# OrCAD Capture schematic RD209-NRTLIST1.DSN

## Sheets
1 4: size A3
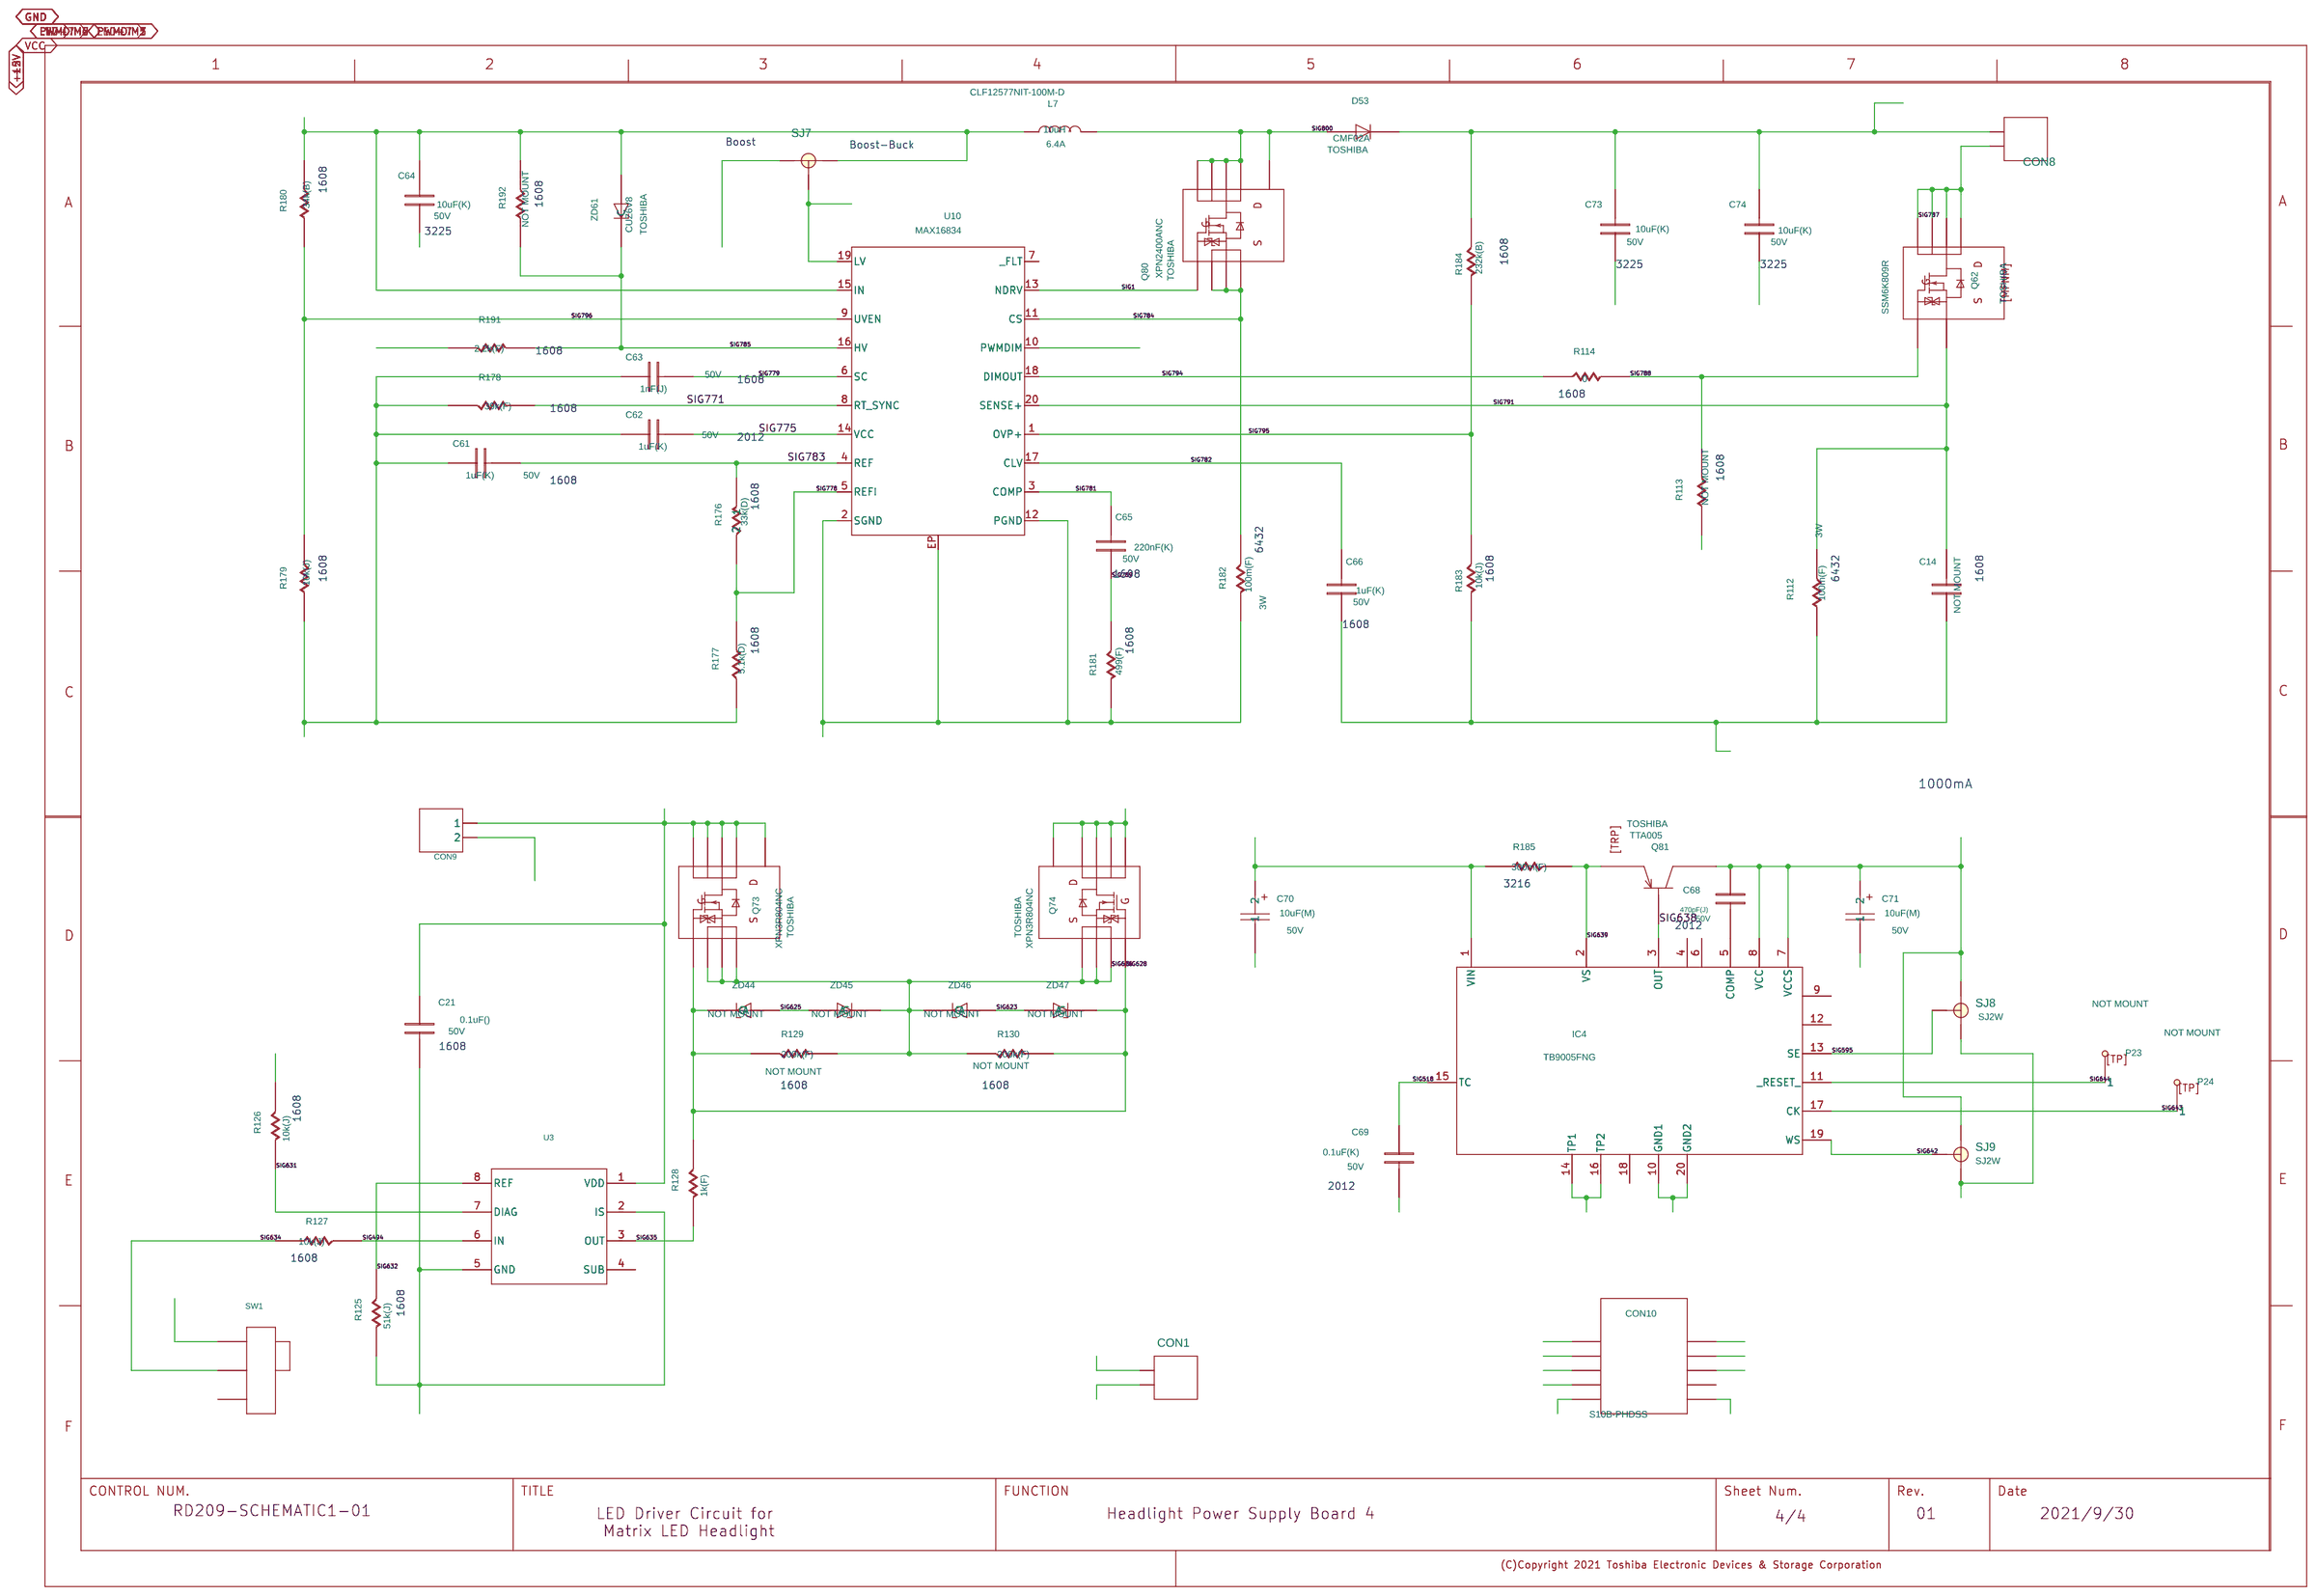
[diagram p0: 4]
2 3: size A3
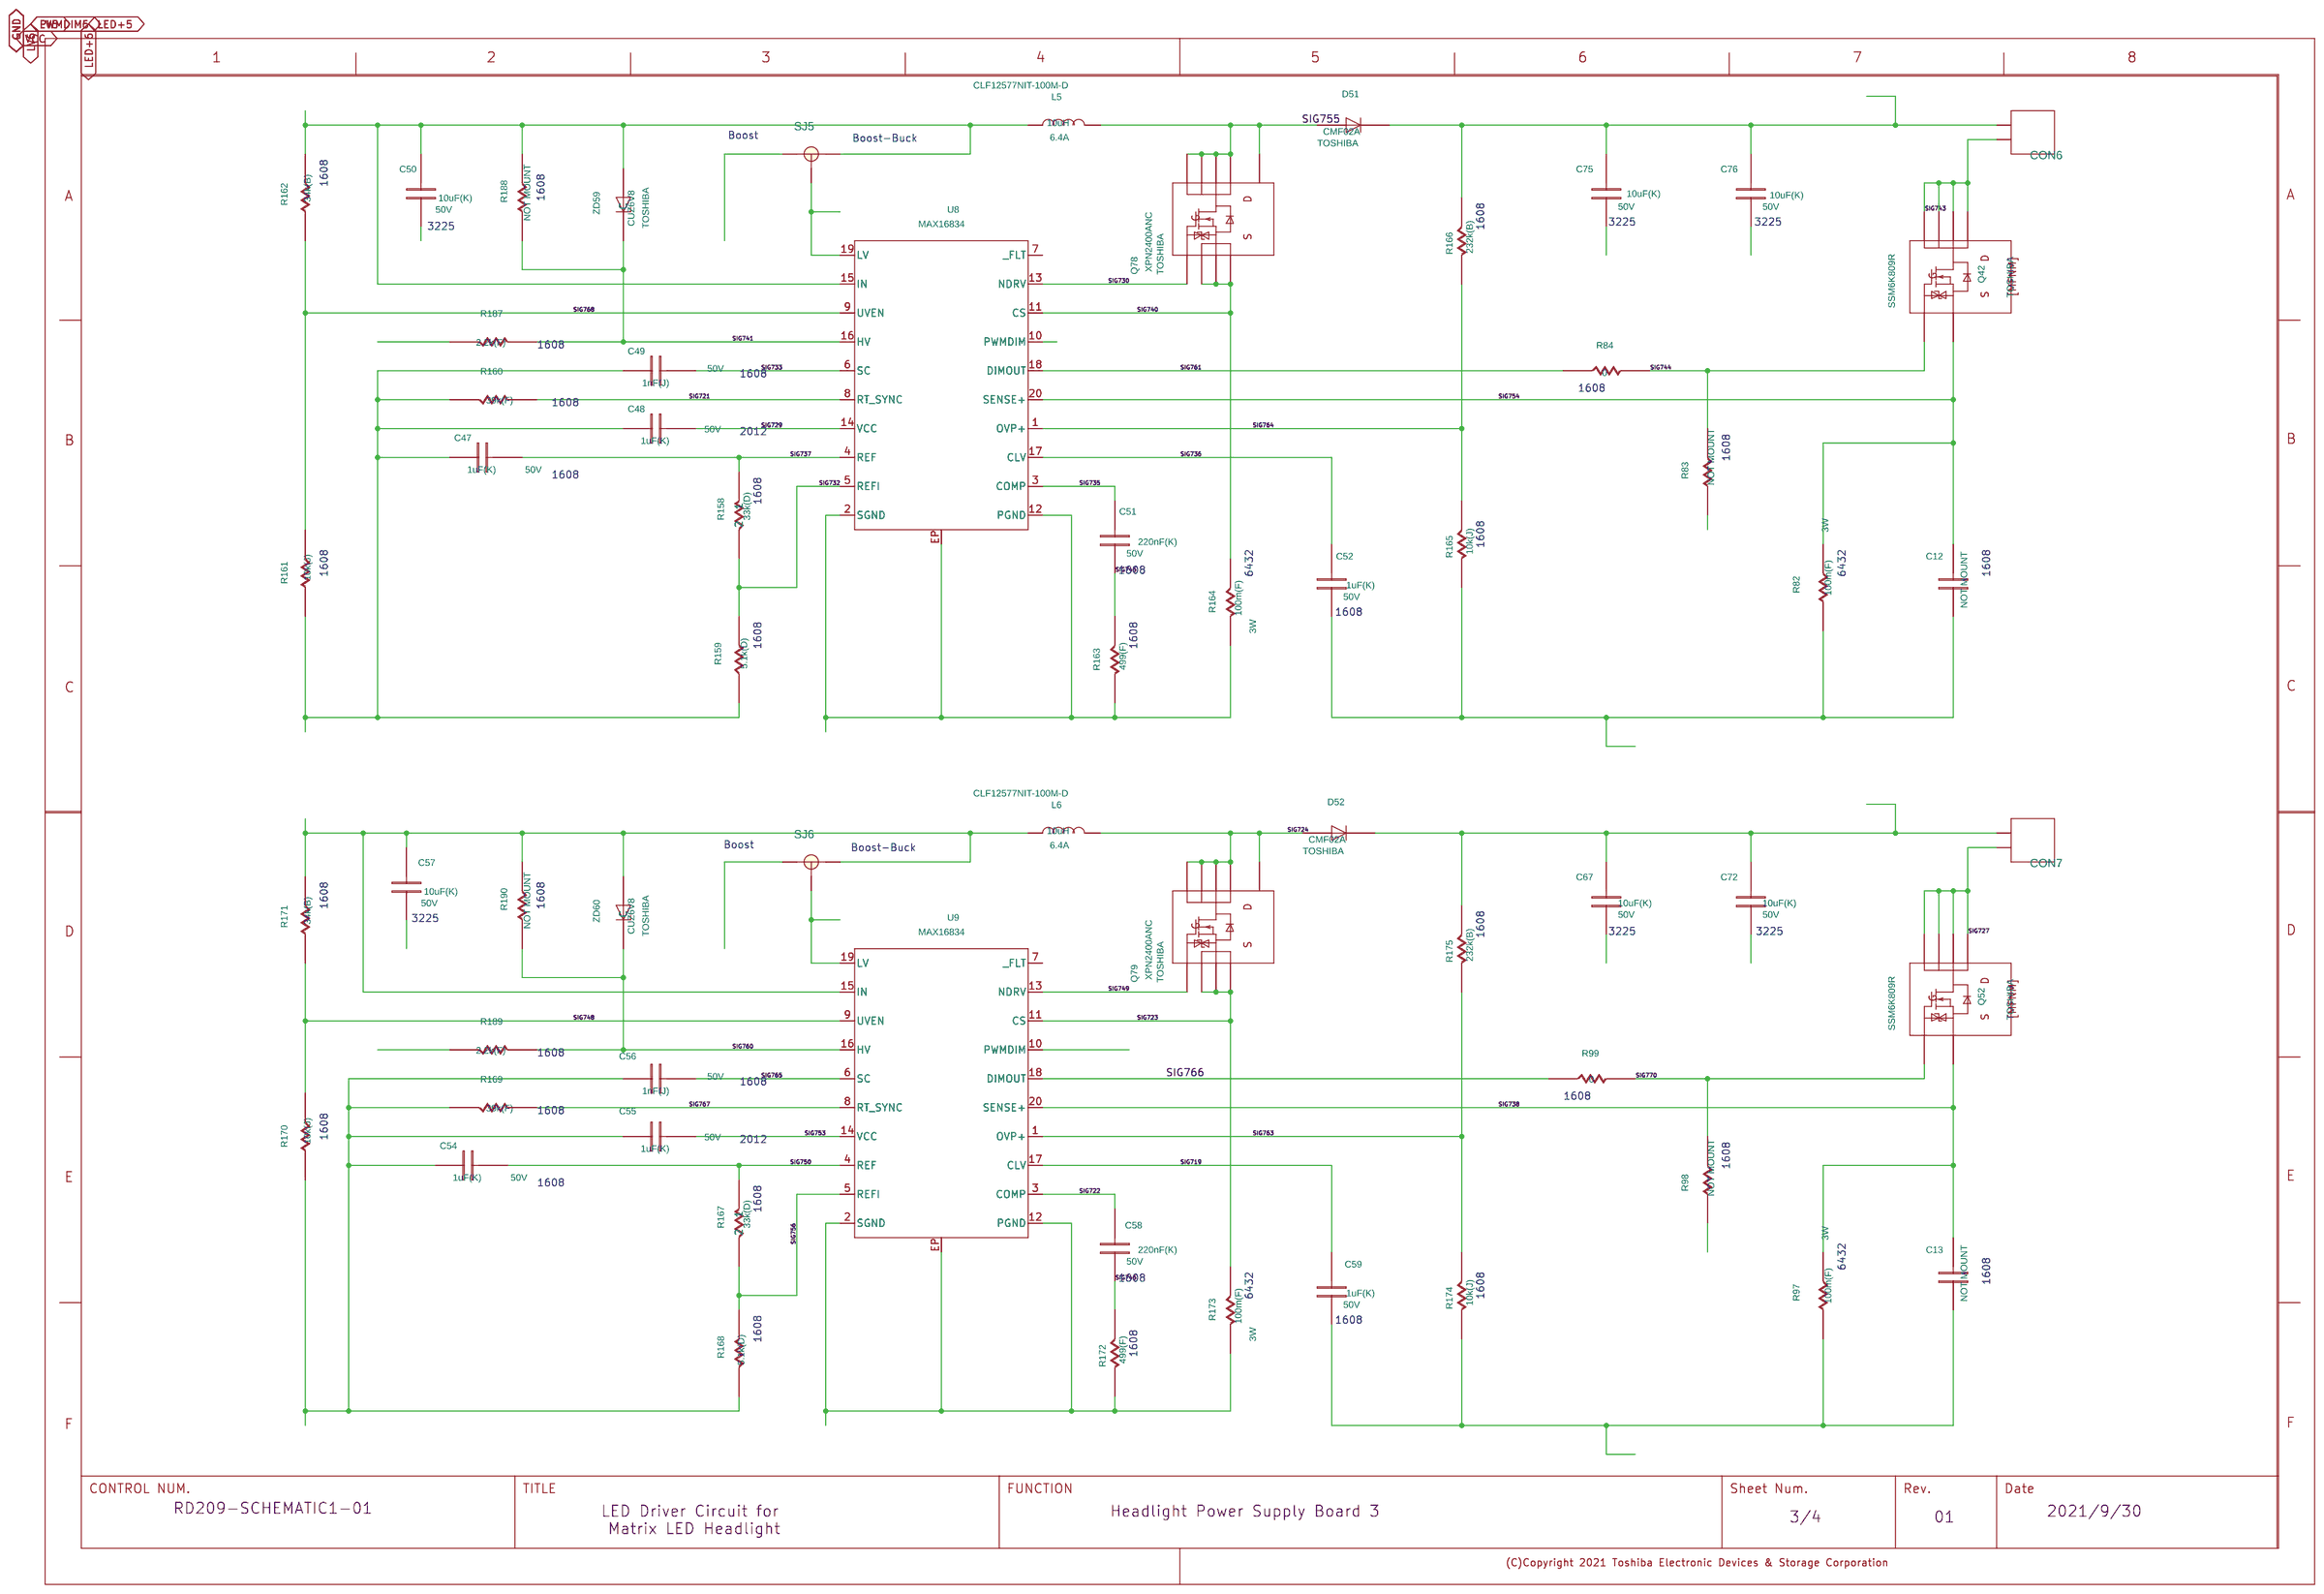
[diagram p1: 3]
3 2: size A3
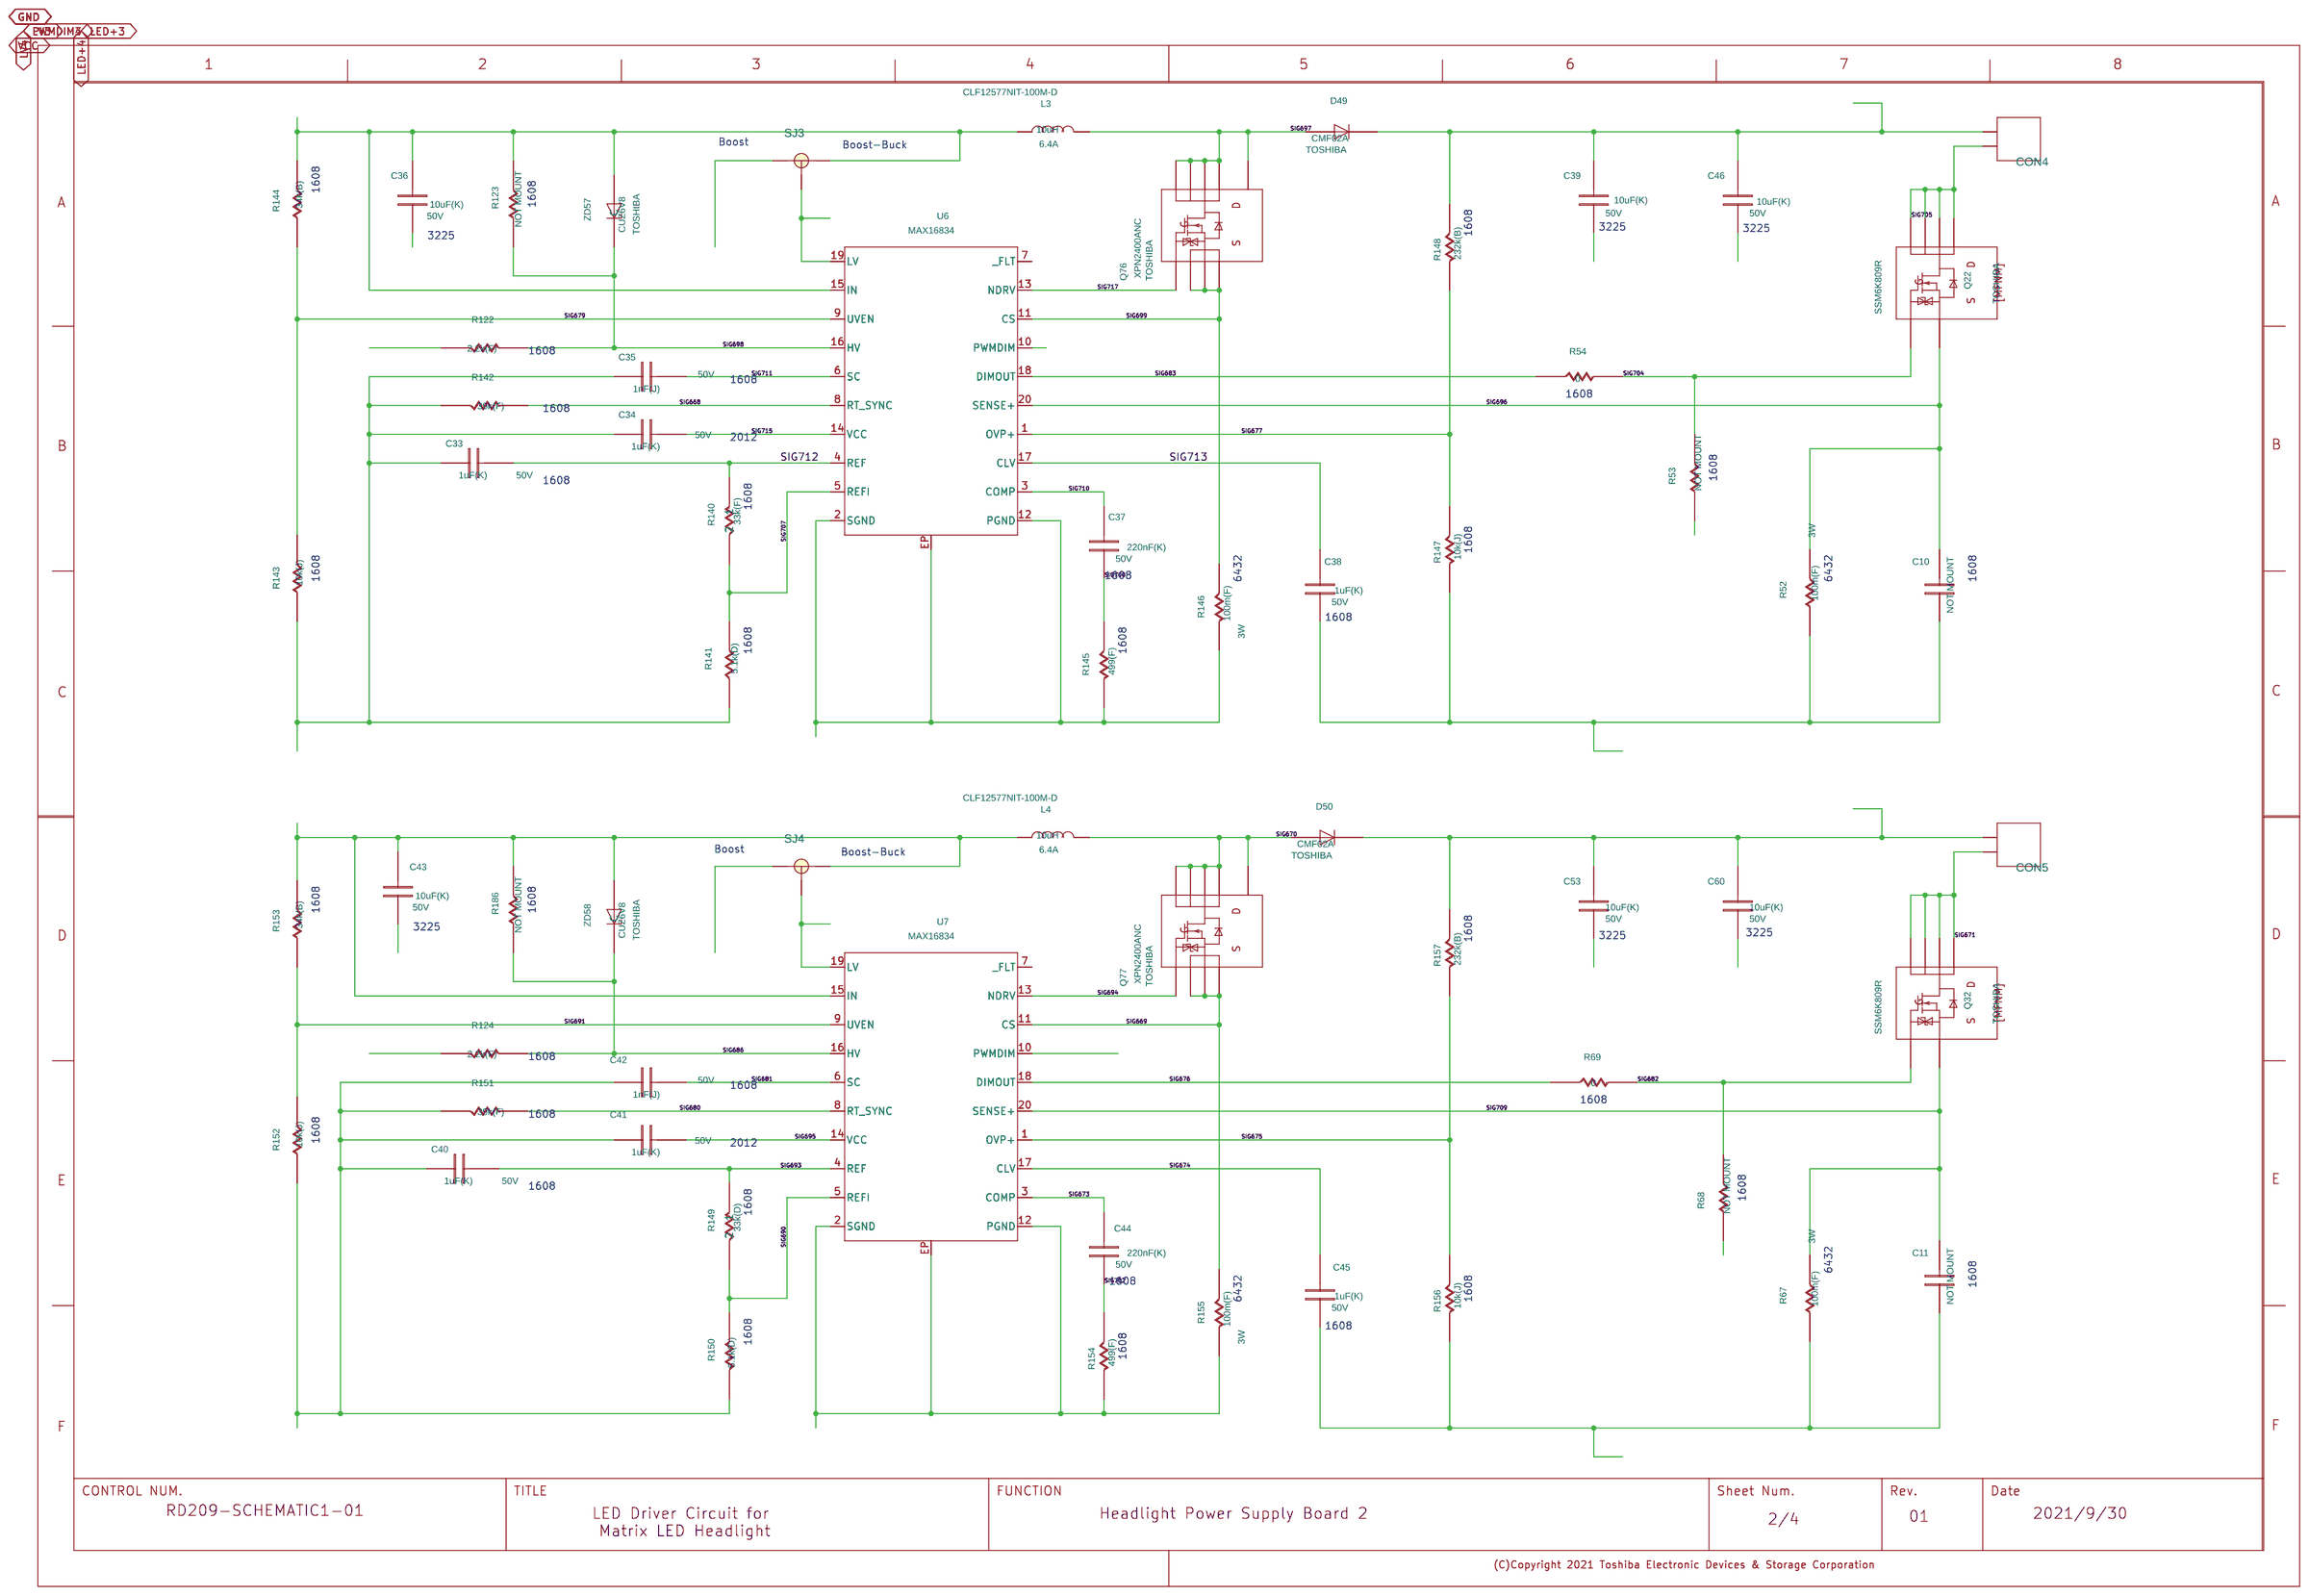
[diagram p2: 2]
4 1: size A3
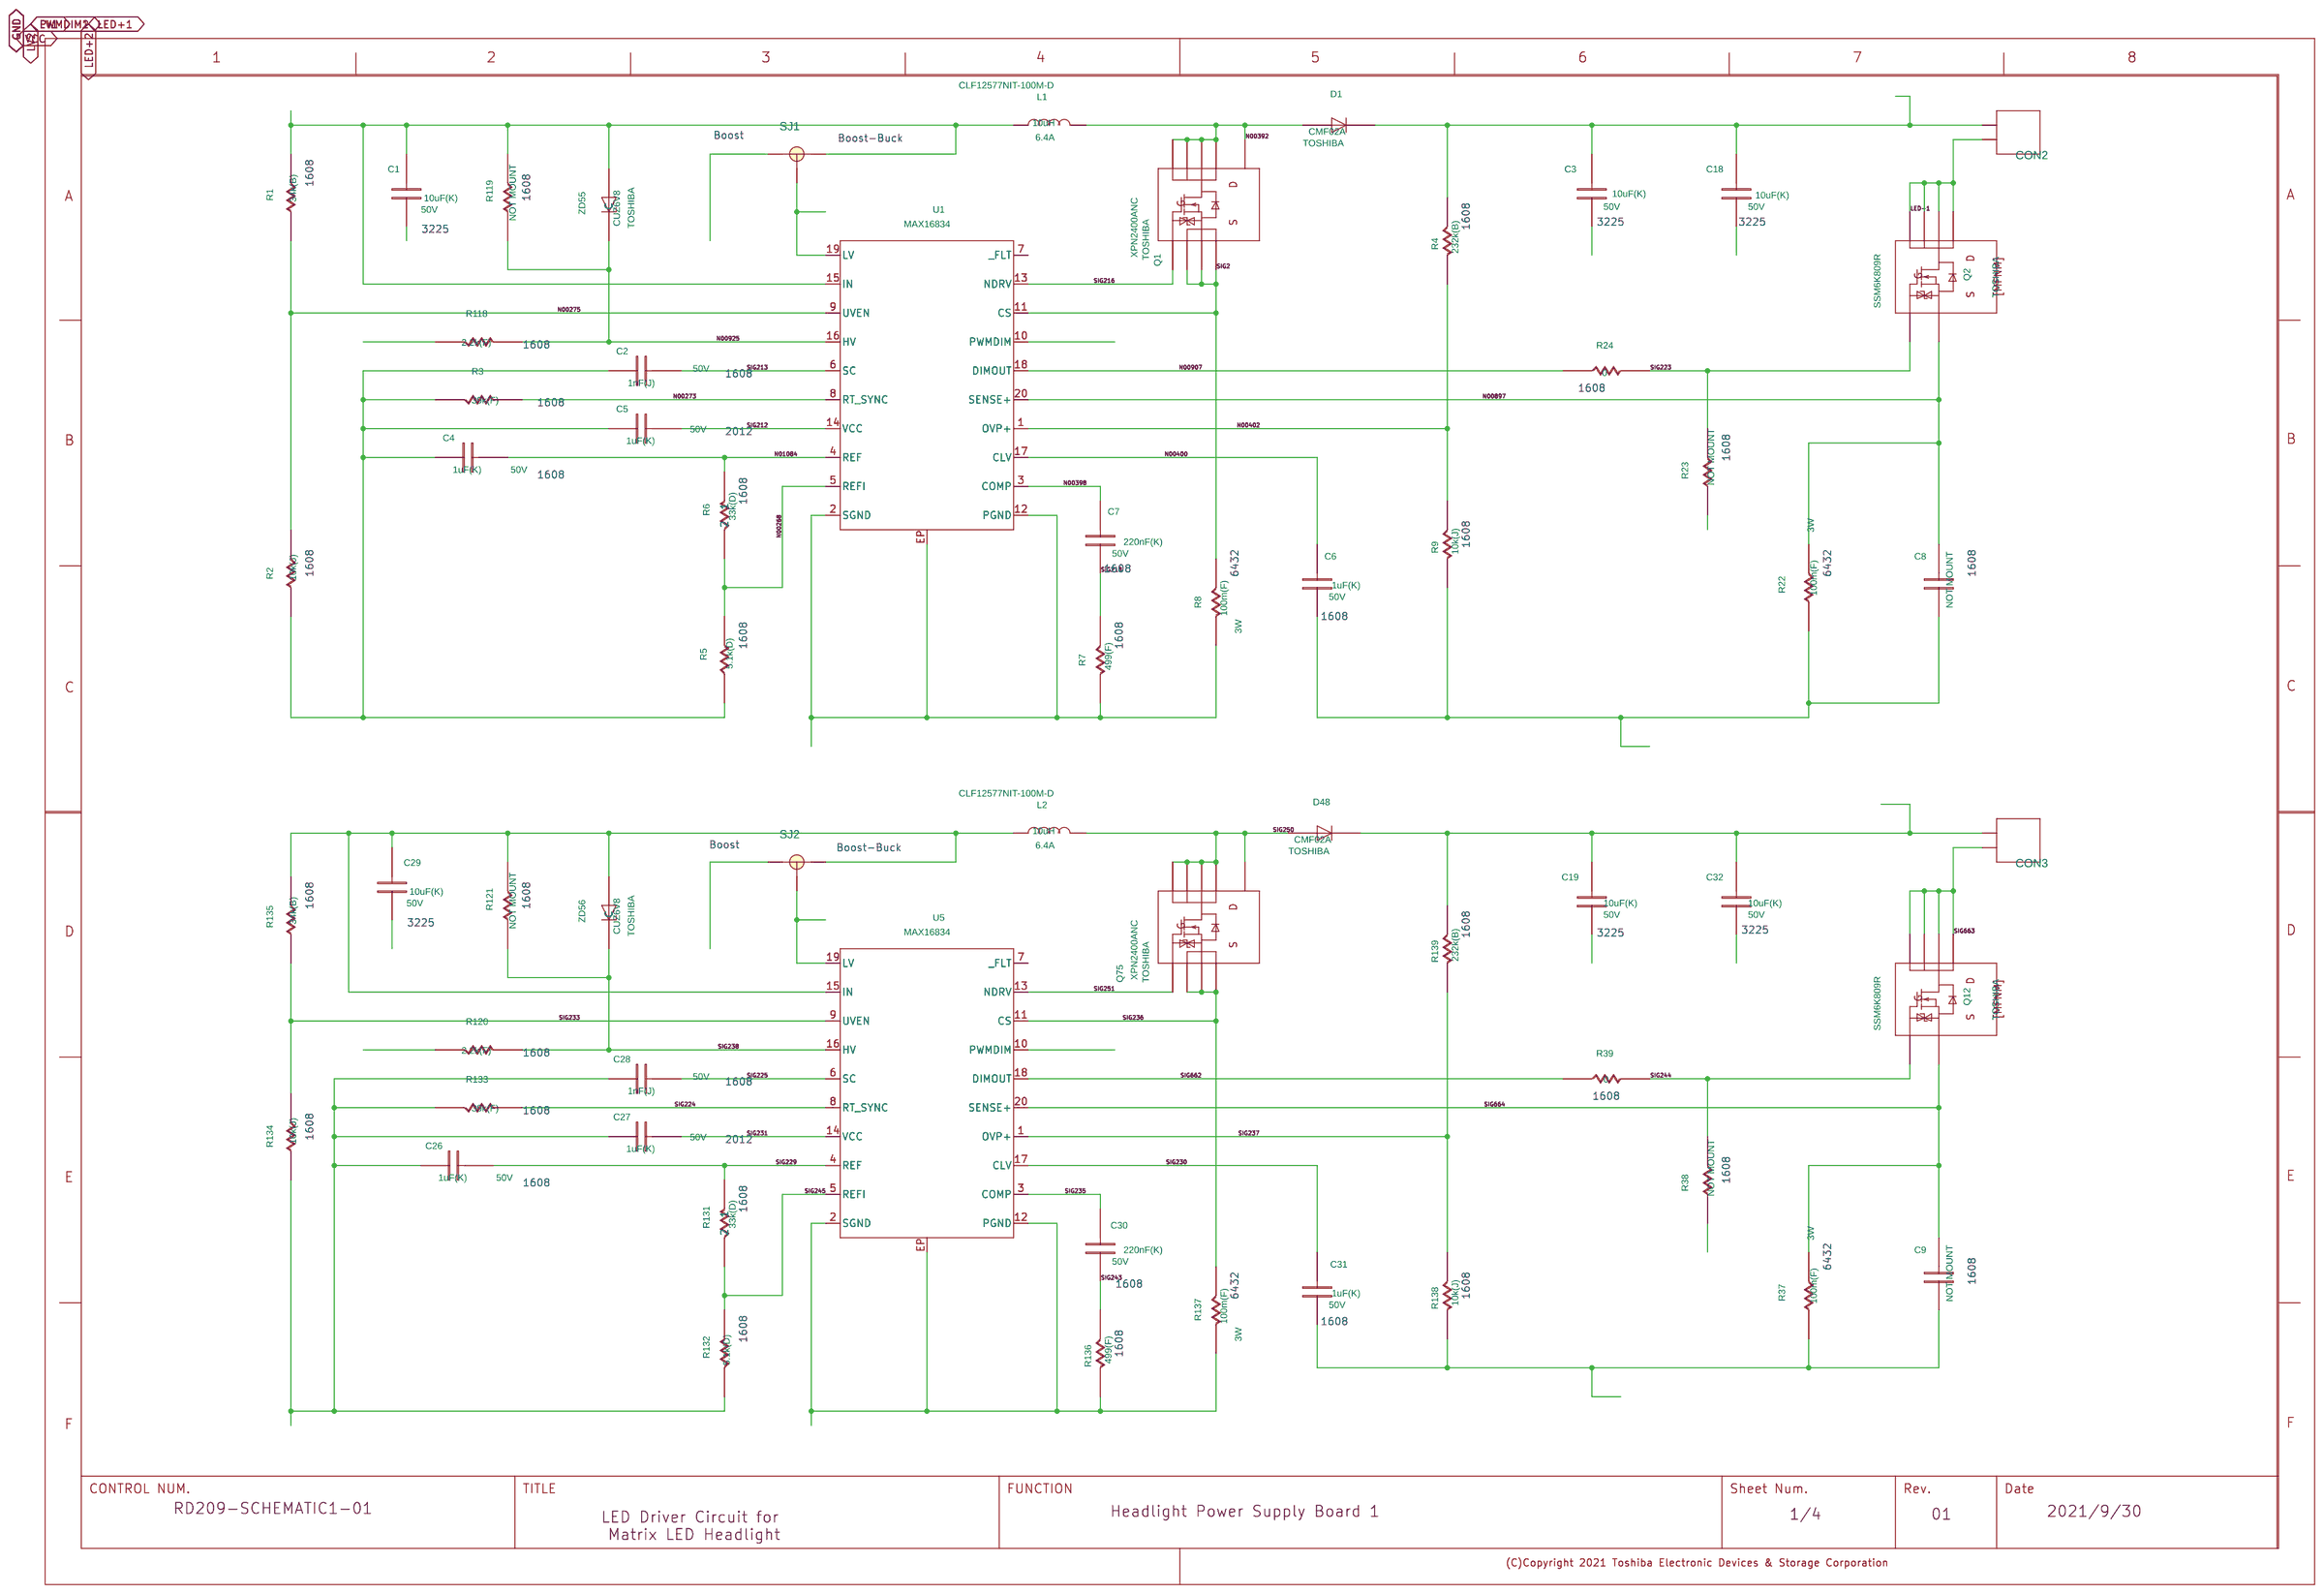
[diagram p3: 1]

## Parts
sheet 1
C1  C
C2  C
C3  C
C4  C
C5  C
C6  C
C7  C
C8  C
C9  C
C18  C
C19  C
C26  C
C27  C
C28  C
C29  C
C30  C
C31  C
C32  C
CON2  B2B-XH-A  [B2B-XH-A]
CON3  B2B-XH-A  [B2B-XH-A]
D1  D
D48  D
L1  L
L2  L
Q1  MFNKR1
Q2  MFNM
Q12  MFNM
Q75  MFNKR1
R1  R
R2  R
R3  R
R4  R
R5  R
R6  R
R7  R
R8  R
R9  R
R22  R
R23  R
R24  R
R37  R
R38  R
R39  R
R118  R
R119  R
R120  R
R121  R
R131  R
R132  R
R133  R
R134  R
R135  R
R136  R
R137  R
R138  R
R139  R
SJ1  SJ2W
SJ2  SJ2W
U1  MAX16834
U5  MAX16834
U?#3  WAKU_DEF100
ZD55  ZD
ZD56  ZD
sheet 2
C10  C
C11  C
C33  C
C34  C
C35  C
C36  C
C37  C
C38  C
C39  C
C40  C
C41  C
C42  C
C43  C
C44  C
C45  C
C46  C
C53  C
C60  C
CON4  B2B-XH-A  [B2B-XH-A]
CON5  B2B-XH-A  [B2B-XH-A]
D49  D
D50  D
L3  L
L4  L
Q22  MFNM
Q32  MFNM
Q76  MFNKR1
Q77  MFNKR1
R52  R
R53  R
R54  R
R67  R
R68  R
R69  R
R122  R
R123  R
R124  R
R140  R
R141  R
R142  R
R143  R
R144  R
R145  R
R146  R
R147  R
R148  R
R149  R
R150  R
R151  R
R152  R
R153  R
R154  R
R155  R
R156  R
R157  R
R186  R
SJ3  SJ2W
SJ4  SJ2W
U6  MAX16834
U7  MAX16834
U?#2  WAKU_DEF100
ZD57  ZD
ZD58  ZD
sheet 3
C12  C
C13  C
C47  C
C48  C
C49  C
C50  C
C51  C
C52  C
C54  C
C55  C
C56  C
C57  C
C58  C
C59  C
C67  C
C72  C
C75  C
C76  C
CON6  B2B-XH-A  [B2B-XH-A]
CON7  B2B-XH-A  [B2B-XH-A]
D51  D
D52  D
L5  L
L6  L
Q42  MFNM
Q52  MFNM
Q78  MFNKR1
Q79  MFNKR1
R82  R
R83  R
R84  R
R97  R
R98  R
R99  R
R158  R
R159  R
R160  R
R161  R
R162  R
R163  R
R164  R
R165  R
R166  R
R167  R
R168  R
R169  R
R170  R
R171  R
R172  R
R173  R
R174  R
R175  R
R187  R
R188  R
R189  R
R190  R
SJ5  SJ2W
SJ6  SJ2W
U8  MAX16834
U9  MAX16834
U?#1  WAKU_DEF100
ZD59  ZD
ZD60  ZD
sheet 4
C14  C
C21  C
C61  C
C62  C
C63  C
C64  C
C65  C
C66  C
C68  C
C69  C
C70  CP
C71  CP
C73  C
C74  C
CON1  B2B-XH-A  [B2B-XH-A]
CON8  B2B-XH-A  [B2B-XH-A]
CON9  B2PS-VH  [B2PS-VH]
CON10  CON10_5X5
D53  D
IC4  TB9005FNG
L7  L
P23  TP
P24  TP
Q62  MFNM
Q73  MFNKR1
Q74  MFNKR1
Q80  MFNKR1
Q81  TRP
R112  R
R113  R
R114  R
R125  R
R126  R
R127  R
R128  R
R129  R
R130  R
R176  R
R177  R
R178  R
R179  R
R180  R
R181  R
R182  R
R183  R
R184  R
R185  R
R191  R
R192  R
SJ7  SJ2W
SJ8  SJ2W
SJ9  SJ2W
SW1  SS-12SDP2  [SS-12SDP2]
U3  TPD7104AF  [PS-8]
U10  MAX16834
U?#4  WAKU_DEF100
ZD44  ZD
ZD45  ZD
ZD46  ZD
ZD47  ZD
ZD61  ZD

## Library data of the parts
C1 = C: CDBNAME: C1210K; COMPONENTTYPE: 4; INSTANCENAME: cmp468; VAL1: 10uF(K); VAL2: 50V
C2 = C: CDBNAME: C0603K_1; COMPONENTTYPE: 4; INSTANCENAME: cmp462; VAL1: 1nF(J); VAL2: 50V
C3 = C: CDBNAME: C1210K; COMPONENTTYPE: 4; INSTANCENAME: cmp474; VAL1: 10uF(K); VAL2: 50V
C4 = C: CDBNAME: C0603K_3; COMPONENTTYPE: 4; INSTANCENAME: cmp457; VAL1: 1uF(K); VAL2: 50V
C5 = C: CDBNAME: C0805K_1; COMPONENTTYPE: 4; INSTANCENAME: cmp459; VAL1: 1uF(K); VAL2: 50V
C6 = C: CDBNAME: C0603K_3; COMPONENTTYPE: 4; INSTANCENAME: cmp481; VAL1: 1uF(K); VAL2: 50V
C7 = C: CDBNAME: C0603K_4; COMPONENTTYPE: 4; INSTANCENAME: cmp482; VAL1: 220nF(K); VAL2: 50V
C8 = C: CDBNAME: C0603K; COMPONENTTYPE: 4; INSTANCENAME: cmp493; NOTMOUNT: NOT MOUNT
C9 = C: CDBNAME: C0603K; COMPONENTTYPE: 4; INSTANCENAME: cmp590; NOTMOUNT: NOT MOUNT
C18 = C: CDBNAME: C1210K; COMPONENTTYPE: 4; INSTANCENAME: cmp472; VAL1: 10uF(K); VAL2: 50V
C19 = C: CDBNAME: C1210K; COMPONENTTYPE: 4; INSTANCENAME: cmp593; VAL1: 10uF(K); VAL2: 50V
C26 = C: CDBNAME: C0603K_3; COMPONENTTYPE: 4; INSTANCENAME: cmp560; VAL1: 1uF(K); VAL2: 50V
C27 = C: CDBNAME: C0805K_1; COMPONENTTYPE: 4; INSTANCENAME: cmp586; VAL1: 1uF(K); VAL2: 50V
C28 = C: CDBNAME: C0603K_1; COMPONENTTYPE: 4; INSTANCENAME: cmp596; VAL1: 1nF(J); VAL2: 50V
C29 = C: CDBNAME: C1210K; COMPONENTTYPE: 4; INSTANCENAME: cmp558; VAL1: 10uF(K); VAL2: 50V
C30 = C: CDBNAME: C0603K_4; COMPONENTTYPE: 4; INSTANCENAME: cmp562; VAL1: 220nF(K); VAL2: 50V
C31 = C: CDBNAME: C0603K_3; COMPONENTTYPE: 4; INSTANCENAME: cmp584; VAL1: 1uF(K); VAL2: 50V
C32 = C: CDBNAME: C1210K; COMPONENTTYPE: 4; INSTANCENAME: cmp554; VAL1: 10uF(K); VAL2: 50V
CON2 CON3 CON8 = B2B_XH_A: COMP: B2_BX_HA; COMPONENTKIND: 135; COMPONENTNAME: CON; COMPONENTTYPE: 4; FUNCN: CON; INSTANCENAME: INS9160
D1 D48-D53 = D: CDBNAME: M-FLAT; COMP: M-FLAT; COMPONENTTYPE: 4; USERCOMPTEXT3: TOSHIBA; VAL1: CMF02A; VAL3: CMF02A
L1 = L: CDBNAME: CLF12577NI-D; COMP: CLF12577NI_D; COMPONENTTYPE: 4; INSTANCENAME: cmp470; VAL1: 10uH; VAL2: 6.4A; VAL3: CLF12577NIT-100M-D
L2 = L: CDBNAME: CLF12577NI-D; COMP: CLF12577NI_D; COMPONENTTYPE: 4; INSTANCENAME: cmp575; VAL1: 10uH; VAL2: 6.4A; VAL3: CLF12577NIT-100M-D
Q1 Q75-Q80 = MFNKR1: CDBNAME: TSON_ADVANCE_WF_1; COMP: TSON_ADVANCE_WF_1; COMPONENTNAME: Q; COMPONENTTYPE: 4; FUNCN: Q; USERCOMPTEXT3: TOSHIBA; VAL1: XPN2400ANC; VAL3: XPN2400ANC
Q2 = MFNM: CDBNAME: TSOP6F; COMP: SSM6K809R; COMPONENTNAME: Q; COMPONENTTYPE: 4; FUNCN: Q; INSTANCENAME: cmp496; USERCOMPTEXT3: TOSHIBA; VAL1: SSM6K809R; VAL3: SSM6K809R
Q12 = MFNM: CDBNAME: TSOP6F; COMP: SSM6K809R; COMPONENTNAME: Q; COMPONENTTYPE: 4; FUNCN: Q; INSTANCENAME: cmp553; USERCOMPTEXT3: TOSHIBA; VAL1: SSM6K809R; VAL3: SSM6K809R
R1 = R: CDBNAME: R0603_1; COMPONENTTYPE: 4; INSTANCENAME: cmp447; VAL1: 34k(B); VAL2: 100mW
R2 = R: CDBNAME: R0603_6; COMPONENTTYPE: 4; INSTANCENAME: cmp448; VAL1: 10k(J); VAL2: 100mW
R3 = R: CDBNAME: R0603_8; COMPONENTTYPE: 4; INSTANCENAME: cmp460; VAL1: 39k(F); VAL2: 100mW
R4 = R: CDBNAME: R0603_9; COMPONENTTYPE: 4; INSTANCENAME: cmp478; VAL1: 232k(B); VAL2: 63mW
R5 = R: CDBNAME: R0603_10; COMPONENTTYPE: 4; INSTANCENAME: cmp450; VAL1: 5.1k(D); VAL2: 100mW
R6 = R#1: CDBNAME: R0603_11; COMPONENTTYPE: 4; CaptureCellPackProp: R##1; INSTANCENAME: cmp606; VAL1: 33k(D); VAL2: 100mW
R7 = R: CDBNAME: R0603_12; COMPONENTTYPE: 4; INSTANCENAME: cmp483; VAL1: 499(F); VAL2: 125mW
R8 = R: CDBNAME: R2512; COMPONENTTYPE: 4; INSTANCENAME: cmp484; VAL1: 100m(F); VAL2: 3W
R9 = R: CDBNAME: R0603_6; COMPONENTTYPE: 4; INSTANCENAME: cmp479; VAL1: 10k(J); VAL2: 100mW
R22 = R: CDBNAME: R2512; COMPONENTTYPE: 4; INSTANCENAME: cmp492; VAL1: 100m(F); VAL2: 3W
R23 = R: CDBNAME: R0603; COMPONENTTYPE: 4; INSTANCENAME: cmp489; NOTMOUNT: NOT MOUNT
R24 = R: CDBNAME: R0603_7; COMPONENTTYPE: 4; INSTANCENAME: cmp498; VAL1: 0
R37 = R: CDBNAME: R2512; COMPONENTTYPE: 4; INSTANCENAME: cmp559; VAL1: 100m(F); VAL2: 3W
R38 = R: CDBNAME: R0603; COMPONENTTYPE: 4; INSTANCENAME: cmp592; NOTMOUNT: NOT MOUNT
R39 = R: CDBNAME: R0603_7; COMPONENTTYPE: 4; INSTANCENAME: cmp550; VAL1: 0
R118 = R: CDBNAME: R0603_2; COMPONENTTYPE: 4; INSTANCENAME: cmp466; VAL1: 2.2k(F); VAL2: 100mW
R119 = R: CDBNAME: R0603; COMPONENTTYPE: 4; INSTANCENAME: cmp469; NOTMOUNT: NOT MOUNT
R120 = R: CDBNAME: R0603_2; COMPONENTTYPE: 4; INSTANCENAME: cmp591; VAL1: 2.2k(F); VAL2: 100mW
R121 = R: CDBNAME: R0603; COMPONENTTYPE: 4; INSTANCENAME: cmp582; NOTMOUNT: NOT MOUNT
R131 = R#1: CDBNAME: R0603_11; COMPONENTTYPE: 4; CaptureCellPackProp: R##1; INSTANCENAME: cmp607; VAL1: 33k(D); VAL2: 100mW
R132 = R: CDBNAME: R0603_10; COMPONENTTYPE: 4; INSTANCENAME: cmp551; VAL1: 5.1k(D); VAL2: 100mW
R133 = R: CDBNAME: R0603_8; COMPONENTTYPE: 4; INSTANCENAME: cmp579; VAL1: 39k(F); VAL2: 100mW
R134 = R: CDBNAME: R0603_6; COMPONENTTYPE: 4; INSTANCENAME: cmp595; VAL1: 10k(J); VAL2: 100mW
R135 = R: CDBNAME: R0603_1; COMPONENTTYPE: 4; INSTANCENAME: cmp561; VAL1: 34k(B); VAL2: 100mW
R136 = R: CDBNAME: R0603_12; COMPONENTTYPE: 4; INSTANCENAME: cmp555; VAL1: 499(F); VAL2: 125mW
R137 = R: CDBNAME: R2512; COMPONENTTYPE: 4; INSTANCENAME: cmp571; VAL1: 100m(F); VAL2: 3W
R138 = R: CDBNAME: R0603_6; COMPONENTTYPE: 4; INSTANCENAME: cmp564; VAL1: 10k(J); VAL2: 100mW
R139 = R: CDBNAME: R0603_9; COMPONENTTYPE: 4; INSTANCENAME: cmp581; VAL1: 232k(B); VAL2: 63mW
SJ1 = SJ2W: CDBNAME: SJ_2; COMP: SJ_2; COMPONENTKIND: 120; COMPONENTNAME: SJ; COMPONENTTYPE: 4; FUNCN: SJ; INSTANCENAME: cmp600
SJ2 = SJ2W: CDBNAME: SJ_2; COMP: SJ_2; COMPONENTKIND: 120; COMPONENTNAME: SJ; COMPONENTTYPE: 4; FUNCN: SJ; INSTANCENAME: cmp604
U1 U5-U10 = MAX16834: CDBNAME: 20-TQFN; COMP: 20-TQFN; COMPONENTKIND: 101; COMPONENTNAME: IC; COMPONENTTYPE: 4; FUNCN: IC; INSTANCENAME: cmp580
U?#3 = WAKU_DEF100: COMPONENTTYPE: 2; DATE: 2021/9/30; DRAWINGNUMBER: RD209-SCHEMATIC1-01; FUNCTION: Headlight Power Supply Board 1; REVISION: 01; SHEETNUMBER: 1/4; TITLE: LED Driver Circuit for / Matrix LED Headlight; UPDATEDATE: 2021/09/30; UPDATETIME: 12:50:54
ZD55 = ZD: CDBNAME: USC; COMPONENTTYPE: 4; INSTANCENAME: cmp445; USERCOMPTEXT3: TOSHIBA; VAL1: CUZ6V8; VAL3: CUZ6V8
ZD56 = ZD: CDBNAME: USC; COMPONENTTYPE: 4; INSTANCENAME: cmp588; USERCOMPTEXT3: TOSHIBA; VAL1: CUZ6V8; VAL3: CUZ6V8
C10 = C: CDBNAME: C0603K; COMPONENTTYPE: 4; INSTANCENAME: cmp621; NOTMOUNT: NOT MOUNT
C11 = C: CDBNAME: C0603K; COMPONENTTYPE: 4; INSTANCENAME: cmp618; NOTMOUNT: NOT MOUNT
C33 = C: CDBNAME: C0603K_3; COMPONENTTYPE: 4; INSTANCENAME: cmp640; VAL1: 1uF(K); VAL2: 50V
C34 = C: CDBNAME: C0805K_1; COMPONENTTYPE: 4; INSTANCENAME: cmp563; VAL1: 1uF(K); VAL2: 50V
C35 = C: CDBNAME: C0603K_1; COMPONENTTYPE: 4; INSTANCENAME: cmp588; VAL1: 1nF(J); VAL2: 50V
C36 = C: CDBNAME: C1210K; COMPONENTTYPE: 4; INSTANCENAME: cmp623; VAL1: 10uF(K); VAL2: 50V
C37 = C: CDBNAME: C0603K_4; COMPONENTTYPE: 4; INSTANCENAME: cmp596; VAL1: 220nF(K); VAL2: 50V
C38 = C: CDBNAME: C0603K_3; COMPONENTTYPE: 4; INSTANCENAME: cmp624; VAL1: 1uF(K); VAL2: 50V
C39 = C: CDBNAME: C1210K; COMPONENTTYPE: 4; INSTANCENAME: cmp589; VAL1: 10uF(K); VAL2: 50V
C40 = C: CDBNAME: C0603K_3; COMPONENTTYPE: 4; INSTANCENAME: cmp634; VAL1: 1uF(K); VAL2: 50V
C41 = C: CDBNAME: C0805K_1; COMPONENTTYPE: 4; INSTANCENAME: cmp629; VAL1: 1uF(K); VAL2: 50V
C42 = C: CDBNAME: C0603K_1; COMPONENTTYPE: 4; INSTANCENAME: cmp601; VAL1: 1nF(J); VAL2: 50V
C43 = C: CDBNAME: C1210K; COMPONENTTYPE: 4; INSTANCENAME: cmp574; VAL1: 10uF(K); VAL2: 50V
C44 = C: CDBNAME: C0603K_4; COMPONENTTYPE: 4; INSTANCENAME: cmp606; VAL1: 220nF(K); VAL2: 50V
C45 = C: CDBNAME: C0603K_3; COMPONENTTYPE: 4; INSTANCENAME: cmp592; VAL1: 1uF(K); VAL2: 50V
C46 = C: CDBNAME: C1210K; COMPONENTTYPE: 4; INSTANCENAME: cmp643; VAL1: 10uF(K); VAL2: 50V
C53 = C: CDBNAME: C1210K; COMPONENTTYPE: 4; INSTANCENAME: cmp642; VAL1: 10uF(K); VAL2: 50V
C60 = C: CDBNAME: C1210K; COMPONENTTYPE: 4; INSTANCENAME: cmp627; VAL1: 10uF(K); VAL2: 50V
CON4-CON7 = B2B_XH_A: COMP: B2_BX_HA; COMPONENTNAME: CON; COMPONENTTYPE: 4; FUNCN: CON; INSTANCENAME: INS9160
L3 = L: CDBNAME: CLF12577NI-D; COMP: CLF12577NI_D; COMPONENTTYPE: 4; INSTANCENAME: cmp573; VAL1: 10uH; VAL2: 6.4A; VAL3: CLF12577NIT-100M-D
L4 = L: CDBNAME: CLF12577NI-D; COMP: CLF12577NI_D; COMPONENTTYPE: 4; INSTANCENAME: cmp646; VAL1: 10uH; VAL2: 6.4A; VAL3: CLF12577NIT-100M-D
Q22 = MFNM: CDBNAME: TSOP6F; COMP: SSM6K809R; COMPONENTNAME: Q; COMPONENTTYPE: 4; FUNCN: Q; INSTANCENAME: cmp648; USERCOMPTEXT3: TOSHIBA; VAL1: SSM6K809R; VAL3: SSM6K809R
Q32 = MFNM: CDBNAME: TSOP6F; COMP: SSM6K809R; COMPONENTNAME: Q; COMPONENTTYPE: 4; FUNCN: Q; INSTANCENAME: cmp571; USERCOMPTEXT3: TOSHIBA; VAL1: SSM6K809R; VAL3: SSM6K809R
R52 = R: CDBNAME: R2512; COMPONENTTYPE: 4; INSTANCENAME: cmp587; VAL1: 100m(F); VAL2: 3W
R53 = R: CDBNAME: R0603; COMPONENTTYPE: 4; INSTANCENAME: cmp639; NOTMOUNT: NOT MOUNT
R54 = R: CDBNAME: R0603_7; COMPONENTTYPE: 4; INSTANCENAME: cmp605; VAL1: 0
R67 = R: CDBNAME: R2512; COMPONENTTYPE: 4; INSTANCENAME: cmp568; VAL1: 100m(F); VAL2: 3W
R68 = R: CDBNAME: R0603; COMPONENTTYPE: 4; INSTANCENAME: cmp636; NOTMOUNT: NOT MOUNT
R69 = R: CDBNAME: R0603_7; COMPONENTTYPE: 4; INSTANCENAME: cmp595; VAL1: 0
R122 = R: CDBNAME: R0603_2; COMPONENTTYPE: 4; INSTANCENAME: cmp617; VAL1: 2.2k(F); VAL2: 100mW
R123 = R: CDBNAME: R0603; COMPONENTTYPE: 4; INSTANCENAME: cmp598; NOTMOUNT: NOT MOUNT
R124 = R: CDBNAME: R0603_2; COMPONENTTYPE: 4; INSTANCENAME: cmp619; VAL1: 2.2k(F); VAL2: 100mW
R140 = R#1: CDBNAME: R0603_11; COMPONENTTYPE: 4; CaptureCellPackProp: R##1; INSTANCENAME: cmp630; VAL1: 33k(F); VAL2: 100mW
R141 = R: CDBNAME: R0603_10; COMPONENTTYPE: 4; INSTANCENAME: cmp599; VAL1: 5.1k(D); VAL2: 100mW
R142 = R: CDBNAME: R0603_8; COMPONENTTYPE: 4; INSTANCENAME: cmp580; VAL1: 39k(F); VAL2: 100mW
R143 = R: CDBNAME: R0603_6; COMPONENTTYPE: 4; INSTANCENAME: cmp590; VAL1: 10k(J); VAL2: 100mW
R144 = R: CDBNAME: R0603_1; COMPONENTTYPE: 4; INSTANCENAME: cmp616; VAL1: 34k(B); VAL2: 100mW
R145 = R: CDBNAME: R0603_12; COMPONENTTYPE: 4; INSTANCENAME: cmp614; VAL1: 499(F); VAL2: 125mW
R146 = R: CDBNAME: R2512; COMPONENTTYPE: 4; INSTANCENAME: cmp631; VAL1: 100m(F); VAL2: 3W
R147 = R: CDBNAME: R0603_6; COMPONENTTYPE: 4; INSTANCENAME: cmp608; VAL1: 10k(J); VAL2: 100mW
R148 = R: CDBNAME: R0603_9; COMPONENTTYPE: 4; INSTANCENAME: cmp625; VAL1: 232k(B); VAL2: 63mW
R149 = R#1: CDBNAME: R0603_11; COMPONENTTYPE: 4; CaptureCellPackProp: R##1; INSTANCENAME: cmp612; VAL1: 33k(D); VAL2: 100mW
R150 = R: CDBNAME: R0603_10; COMPONENTTYPE: 4; INSTANCENAME: cmp594; VAL1: 5.1k(D); VAL2: 100mW
R151 = R: CDBNAME: R0603_8; COMPONENTTYPE: 4; INSTANCENAME: cmp583; VAL1: 39k(F); VAL2: 100mW
R152 = R: CDBNAME: R0603_6; COMPONENTTYPE: 4; INSTANCENAME: cmp577; VAL1: 10k(J); VAL2: 100mW
R153 = R: CDBNAME: R0603_1; COMPONENTTYPE: 4; INSTANCENAME: cmp610; VAL1: 34k(B); VAL2: 100mW
R154 = R: CDBNAME: R0603_12; COMPONENTTYPE: 4; INSTANCENAME: cmp604; VAL1: 499(F); VAL2: 125mW
R155 = R: CDBNAME: R2512; COMPONENTTYPE: 4; INSTANCENAME: cmp597; VAL1: 100m(F); VAL2: 3W
R156 = R: CDBNAME: R0603_6; COMPONENTTYPE: 4; INSTANCENAME: cmp586; VAL1: 10k(J); VAL2: 100mW
R157 = R: CDBNAME: R0603_9; COMPONENTTYPE: 4; INSTANCENAME: cmp611; VAL1: 232k(B); VAL2: 63mW
R186 = R: CDBNAME: R0603; COMPONENTTYPE: 4; INSTANCENAME: cmp644; NOTMOUNT: NOT MOUNT
SJ3 = SJ2W: CDBNAME: SJ_2; COMP: SJ_2; COMPONENTNAME: SJ; COMPONENTTYPE: 4; FUNCN: SJ; INSTANCENAME: cmp613
SJ4 = SJ2W: CDBNAME: SJ_2; COMP: SJ_2; COMPONENTNAME: SJ; COMPONENTTYPE: 4; FUNCN: SJ; INSTANCENAME: cmp566
U?#2 = WAKU_DEF100: COMPONENTTYPE: 2; DATE: 2021/9/30; DRAWINGNUMBER: RD209-SCHEMATIC1-01; FUNCTION: Headlight Power Supply Board 2; REVISION: 01; SHEETNUMBER: 2/4; TITLE: LED Driver Circuit for / Matrix LED Headlight; UPDATEDATE: 2021/09/30; UPDATETIME: 12:50:54
ZD57 = ZD: CDBNAME: USC; COMPONENTTYPE: 4; INSTANCENAME: cmp582; USERCOMPTEXT3: TOSHIBA; VAL1: CUZ6V8; VAL3: CUZ6V8
ZD58 = ZD: CDBNAME: USC; COMPONENTTYPE: 4; INSTANCENAME: cmp593; USERCOMPTEXT3: TOSHIBA; VAL1: CUZ6V8; VAL3: CUZ6V8
C12 = C: CDBNAME: C0603K; COMPONENTTYPE: 4; INSTANCENAME: cmp123; NOTMOUNT: NOT MOUNT
C13 = C: CDBNAME: C0603K; COMPONENTTYPE: 4; INSTANCENAME: cmp180; NOTMOUNT: NOT MOUNT
C47 = C: CDBNAME: C0603K_3; COMPONENTTYPE: 4; INSTANCENAME: cmp124; VAL1: 1uF(K); VAL2: 50V
C48 = C: CDBNAME: C0805K_1; COMPONENTTYPE: 4; INSTANCENAME: cmp113; VAL1: 1uF(K); VAL2: 50V
C49 = C: CDBNAME: C0603K_1; COMPONENTTYPE: 4; INSTANCENAME: cmp171; VAL1: 1nF(J); VAL2: 50V
C50 = C: CDBNAME: C1210K; COMPONENTTYPE: 4; INSTANCENAME: cmp149; VAL1: 10uF(K); VAL2: 50V
C51 = C: CDBNAME: C0603K_4; COMPONENTTYPE: 4; INSTANCENAME: cmp114; VAL1: 220nF(K); VAL2: 50V
C52 = C: CDBNAME: C0603K_3; COMPONENTTYPE: 4; INSTANCENAME: cmp167; VAL1: 1uF(K); VAL2: 50V
C54 = C: CDBNAME: C0603K_3; COMPONENTTYPE: 4; INSTANCENAME: cmp144; VAL1: 1uF(K); VAL2: 50V
C55 = C: CDBNAME: C0805K_1; COMPONENTTYPE: 4; INSTANCENAME: cmp147; VAL1: 1uF(K); VAL2: 50V
C56 = C: CDBNAME: C0603K_1; COMPONENTTYPE: 4; INSTANCENAME: cmp153; VAL1: 1nF(J); VAL2: 50V
C57 = C: CDBNAME: C1210K; COMPONENTTYPE: 4; INSTANCENAME: cmp166; VAL1: 10uF(K); VAL2: 50V
C58 = C: CDBNAME: C0603K_4; COMPONENTTYPE: 4; INSTANCENAME: cmp119; VAL1: 220nF(K); VAL2: 50V
C59 = C: CDBNAME: C0603K_3; COMPONENTTYPE: 4; INSTANCENAME: cmp148; VAL1: 1uF(K); VAL2: 50V
C67 = C: CDBNAME: C1210K; COMPONENTTYPE: 4; INSTANCENAME: cmp111; VAL1: 10uF(K); VAL2: 50V
C72 = C: CDBNAME: C1210K; COMPONENTTYPE: 4; INSTANCENAME: cmp175; VAL1: 10uF(K); VAL2: 50V
C75 = C: CDBNAME: C1210K; COMPONENTTYPE: 4; INSTANCENAME: cmp157; VAL1: 10uF(K); VAL2: 50V
C76 = C: CDBNAME: C1210K; COMPONENTTYPE: 4; INSTANCENAME: cmp173; VAL1: 10uF(K); VAL2: 50V
L5 = L: CDBNAME: CLF12577NI-D; COMP: CLF12577NI_D; COMPONENTTYPE: 4; INSTANCENAME: cmp146; VAL1: 10uH; VAL2: 6.4A; VAL3: CLF12577NIT-100M-D
L6 = L: CDBNAME: CLF12577NI-D; COMP: CLF12577NI_D; COMPONENTTYPE: 4; INSTANCENAME: cmp190; VAL1: 10uH; VAL2: 6.4A; VAL3: CLF12577NIT-100M-D
Q42 = MFNM: CDBNAME: TSOP6F; COMP: SSM6K809R; COMPONENTNAME: Q; COMPONENTTYPE: 4; FUNCN: Q; INSTANCENAME: cmp117; USERCOMPTEXT3: TOSHIBA; VAL1: SSM6K809R; VAL3: SSM6K809R
Q52 = MFNM: CDBNAME: TSOP6F; COMP: SSM6K809R; COMPONENTNAME: Q; COMPONENTTYPE: 4; FUNCN: Q; INSTANCENAME: cmp187; USERCOMPTEXT3: TOSHIBA; VAL1: SSM6K809R; VAL3: SSM6K809R
R82 = R: CDBNAME: R2512; COMPONENTTYPE: 4; INSTANCENAME: cmp162; VAL1: 100m(F); VAL2: 3W
R83 = R: CDBNAME: R0603; COMPONENTTYPE: 4; INSTANCENAME: cmp181; NOTMOUNT: NOT MOUNT
R84 = R: CDBNAME: R0603_7; COMPONENTTYPE: 4; INSTANCENAME: cmp128; VAL1: 0
R97 = R: CDBNAME: R2512; COMPONENTTYPE: 4; INSTANCENAME: cmp169; VAL1: 100m(F); VAL2: 3W
R98 = R: CDBNAME: R0603; COMPONENTTYPE: 4; INSTANCENAME: cmp125; NOTMOUNT: NOT MOUNT
R99 = R: CDBNAME: R0603_7; COMPONENTTYPE: 4; INSTANCENAME: cmp191; VAL1: 0
R158 = R#1: CDBNAME: R0603_11; COMPONENTTYPE: 4; CaptureCellPackProp: R##1; INSTANCENAME: cmp155; VAL1: 33k(D); VAL2: 100mW
R159 = R: CDBNAME: R0603_10; COMPONENTTYPE: 4; INSTANCENAME: cmp145; VAL1: 5.1k(D); VAL2: 100mW
R160 = R: CDBNAME: R0603_8; COMPONENTTYPE: 4; INSTANCENAME: cmp163; VAL1: 39k(F); VAL2: 100mW
R161 = R: CDBNAME: R0603_6; COMPONENTTYPE: 4; INSTANCENAME: cmp122; VAL1: 10k(J); VAL2: 100mW
R162 = R: CDBNAME: R0603_1; COMPONENTTYPE: 4; INSTANCENAME: cmp136; VAL1: 34k(B); VAL2: 100mW
R163 = R: CDBNAME: R0603_12; COMPONENTTYPE: 4; INSTANCENAME: cmp135; VAL1: 499(F); VAL2: 125mW
R164 = R: CDBNAME: R2512; COMPONENTTYPE: 4; INSTANCENAME: cmp164; VAL1: 100m(F); VAL2: 3W
R165 = R: CDBNAME: R0603_6; COMPONENTTYPE: 4; INSTANCENAME: cmp139; VAL1: 10k(J); VAL2: 100mW
R166 = R: CDBNAME: R0603_9; COMPONENTTYPE: 4; INSTANCENAME: cmp168; VAL1: 232k(B); VAL2: 63mW
R167 = R#1: CDBNAME: R0603_11; COMPONENTTYPE: 4; CaptureCellPackProp: R##1; INSTANCENAME: cmp158; VAL1: 33k(D); VAL2: 100mW
R168 = R: CDBNAME: R0603_10; COMPONENTTYPE: 4; INSTANCENAME: cmp179; VAL1: 5.1k(D); VAL2: 100mW
R169 = R: CDBNAME: R0603_8; COMPONENTTYPE: 4; INSTANCENAME: cmp127; VAL1: 39k(F); VAL2: 100mW
R170 = R: CDBNAME: R0603_6; COMPONENTTYPE: 4; INSTANCENAME: cmp131; VAL1: 10k(J); VAL2: 100mW
R171 = R: CDBNAME: R0603_1; COMPONENTTYPE: 4; INSTANCENAME: cmp116; VAL1: 34k(B); VAL2: 100mW
R172 = R: CDBNAME: R0603_12; COMPONENTTYPE: 4; INSTANCENAME: cmp176; VAL1: 499(F); VAL2: 125mW
R173 = R: CDBNAME: R2512; COMPONENTTYPE: 4; INSTANCENAME: cmp115; VAL1: 100m(F); VAL2: 3W
R174 = R: CDBNAME: R0603_6; COMPONENTTYPE: 4; INSTANCENAME: cmp134; VAL1: 10k(J); VAL2: 100mW
R175 = R: CDBNAME: R0603_9; COMPONENTTYPE: 4; INSTANCENAME: cmp185; VAL1: 232k(B); VAL2: 63mW
R187 = R: CDBNAME: R0603_2; COMPONENTTYPE: 4; INSTANCENAME: cmp109; VAL1: 2.2k(F); VAL2: 100mW
R188 = R: CDBNAME: R0603; COMPONENTTYPE: 4; INSTANCENAME: cmp137; NOTMOUNT: NOT MOUNT
R189 = R: CDBNAME: R0603_2; COMPONENTTYPE: 4; INSTANCENAME: cmp189; VAL1: 2.2k(F); VAL2: 100mW
R190 = R: CDBNAME: R0603; COMPONENTTYPE: 4; INSTANCENAME: cmp156; NOTMOUNT: NOT MOUNT
SJ5 = SJ2W: CDBNAME: SJ_2; COMP: SJ_2; COMPONENTNAME: SJ; COMPONENTTYPE: 4; FUNCN: SJ; INSTANCENAME: cmp132
SJ6 = SJ2W: CDBNAME: SJ_2; COMP: SJ_2; COMPONENTNAME: SJ; COMPONENTTYPE: 4; FUNCN: SJ; INSTANCENAME: cmp196
U?#1 = WAKU_DEF100: COMPONENTTYPE: 2; DATE: 2021/9/30; DRAWINGNUMBER: RD209-SCHEMATIC1-01; FUNCTION: Headlight Power Supply Board 3; REVISION: 01; SHEETNUMBER: 3/4; TITLE: LED Driver Circuit for / Matrix LED Headlight; UPDATEDATE: 2021/09/30; UPDATETIME: 12:50:54
ZD59 = ZD: CDBNAME: USC; COMPONENTTYPE: 4; INSTANCENAME: cmp183; USERCOMPTEXT3: TOSHIBA; VAL1: CUZ6V8; VAL3: CUZ6V8
ZD60 = ZD: CDBNAME: USC; COMPONENTTYPE: 4; INSTANCENAME: cmp192; USERCOMPTEXT3: TOSHIBA; VAL1: CUZ6V8; VAL3: CUZ6V8
C14 = C: CDBNAME: C0603K; COMPONENTTYPE: 4; INSTANCENAME: cmp227; NOTMOUNT: NOT MOUNT
C21 = C: CDBNAME: C0603K_2; COMPONENTTYPE: 4; INSTANCENAME: cmp126; VAL1: 0.1uF(); VAL2: 50V
C61 = C: CDBNAME: C0603K_3; COMPONENTTYPE: 4; INSTANCENAME: cmp225; VAL1: 1uF(K); VAL2: 50V
C62 = C: CDBNAME: C0805K_1; COMPONENTTYPE: 4; INSTANCENAME: cmp205; VAL1: 1uF(K); VAL2: 50V
C63 = C: CDBNAME: C0603K_1; COMPONENTTYPE: 4; INSTANCENAME: cmp236; VAL1: 1nF(J); VAL2: 50V
C64 = C: CDBNAME: C1210K; COMPONENTTYPE: 4; INSTANCENAME: cmp209; VAL1: 10uF(K); VAL2: 50V
C65 = C: CDBNAME: C0603K_4; COMPONENTTYPE: 4; INSTANCENAME: cmp219; VAL1: 220nF(K); VAL2: 50V
C66 = C: CDBNAME: C0603K_3; COMPONENTTYPE: 4; INSTANCENAME: cmp231; VAL1: 1uF(K); VAL2: 50V
C68 = C: CDBNAME: C0805K_2; COMPONENTTYPE: 4; INSTANCENAME: cmp141; VAL1: 470pF(J); VAL2: 50V
C69 = C: CDBNAME: C0805K_3; COMPONENTTYPE: 4; INSTANCENAME: cmp152; VAL1: 0.1uF(K); VAL2: 50V
C70 = CP: CDBNAME: UD-6_3X5_8_NICHICON; COMP: C; COMPONENTNAME: C; COMPONENTTYPE: 4; FUNCN: C; INSTANCENAME: cmp135; VAL1: 10uF(M); VAL2: 50V
C71 = CP: CDBNAME: UD-6_3X5_8_NICHICON; COMP: C; COMPONENTNAME: C; COMPONENTTYPE: 4; FUNCN: C; INSTANCENAME: cmp197; VAL1: 10uF(M); VAL2: 50V
C73 = C: CDBNAME: C1210K; COMPONENTTYPE: 4; INSTANCENAME: cmp220; VAL1: 10uF(K); VAL2: 50V
C74 = C: CDBNAME: C1210K; COMPONENTTYPE: 4; INSTANCENAME: cmp234; VAL1: 10uF(K); VAL2: 50V
CON1 = B2B_XH_A: COMP: B2_BX_HA; COMPONENTKIND: 111; COMPONENTNAME: CON; COMPONENTTYPE: 4; FUNCN: CON; INSTANCENAME: INS9244
CON9 = B2PS_VH: COMPONENTKIND: 135; COMPONENTNAME: CON; COMPONENTTYPE: 4; FUNCN: CON; INSTANCENAME: INS9280
CON10 = CON10_5X5: CDBNAME: GDM220002192; COMPONENTNAME: CON; COMPONENTTYPE: 4; FUNCN: CON; INSTANCENAME: cmp189; VAL1: S10B-PHDSS; VAL3: S10B-PHDSS
IC4 = TB9005FNG: COMPONENTNAME: IC; COMPONENTTYPE: 4; FUNCN: IC
L7 = L: CDBNAME: CLF12577NI-D; COMP: CLF12577NI_D; COMPONENTTYPE: 4; INSTANCENAME: cmp206; VAL1: 10uH; VAL2: 6.4A; VAL3: CLF12577NIT-100M-D
P23 = TP: CDBNAME: CT; COMP: HT; COMPONENTTYPE: 4; INSTANCENAME: cmp147; NOTMOUNT: NOT MOUNT
P24 = TP: CDBNAME: CT; COMP: HT; COMPONENTTYPE: 4; INSTANCENAME: cmp146; NOTMOUNT: NOT MOUNT
Q62 = MFNM: CDBNAME: TSOP6F; COMP: SSM6K809R; COMPONENTNAME: Q; COMPONENTTYPE: 4; FUNCN: Q; INSTANCENAME: cmp215; USERCOMPTEXT3: TOSHIBA; VAL1: SSM6K809R; VAL3: SSM6K809R
Q73 Q74 = MFNKR1: CDBNAME: TSON_ADVANCE_WF_2; COMP: TSON_ADVANCE_WF_2; COMPONENTNAME: Q; COMPONENTTYPE: 4; FUNCN: Q; USERCOMPTEXT3: TOSHIBA; VAL1: XPN3R804NC; VAL3: XPN3R804NC
Q81 = TRP: CDBNAME: TTA005; COMP: TTA005; COMPONENTNAME: Q; COMPONENTTYPE: 4; FUNCN: Q; INSTANCENAME: cmp138; USERCOMPTEXT3: TOSHIBA; VAL1: TTA005; VAL3: TTA005
R112 = R: CDBNAME: R2512; COMPONENTTYPE: 4; INSTANCENAME: cmp226; VAL1: 100m(F); VAL2: 3W
R113 = R: CDBNAME: R0603; COMPONENTTYPE: 4; INSTANCENAME: cmp240; NOTMOUNT: NOT MOUNT
R114 = R: CDBNAME: R0603_7; COMPONENTTYPE: 4; INSTANCENAME: cmp233; VAL1: 0
R125 = R: CDBNAME: R0603_3; COMPONENTTYPE: 4; INSTANCENAME: cmp131; VAL1: 51k(J); VAL2: 100mW
R126 = R: CDBNAME: R0603_6; COMPONENTTYPE: 4; INSTANCENAME: cmp130; VAL1: 10k(J); VAL2: 100mW
R127 = R: CDBNAME: R0603_6; COMPONENTTYPE: 4; INSTANCENAME: cmp132; VAL1: 10k(J); VAL2: 100mW
R128 = R: CDBNAME: R0603_4; COMPONENTTYPE: 4; INSTANCENAME: cmp125; VAL1: 1k(F); VAL2: 125mW
R129 = R: CDBNAME: R0603_5; COMPONENTTYPE: 4; INSTANCENAME: cmp121; NOTMOUNT: NOT MOUNT; VAL1: 200k(F); VAL2: 100mW
R130 = R: CDBNAME: R0603_5; COMPONENTTYPE: 4; INSTANCENAME: cmp120; NOTMOUNT: NOT MOUNT; VAL1: 200k(F); VAL2: 100mW
R176 = R#1: CDBNAME: R0603_11; COMPONENTTYPE: 4; CaptureCellPackProp: R##1; INSTANCENAME: cmp214; VAL1: 33k(D); VAL2: 100mW
R177 = R: CDBNAME: R0603_10; COMPONENTTYPE: 4; INSTANCENAME: cmp208; VAL1: 5.1k(D); VAL2: 100mW
R178 = R: CDBNAME: R0603_8; COMPONENTTYPE: 4; INSTANCENAME: cmp224; VAL1: 39k(F); VAL2: 100mW
R179 = R: CDBNAME: R0603_6; COMPONENTTYPE: 4; INSTANCENAME: cmp228; VAL1: 10k(J); VAL2: 100mW
R180 = R: CDBNAME: R0603_1; COMPONENTTYPE: 4; INSTANCENAME: cmp238; VAL1: 34k(B); VAL2: 100mW
R181 = R: CDBNAME: R0603_12; COMPONENTTYPE: 4; INSTANCENAME: cmp239; VAL1: 499(F); VAL2: 125mW
R182 = R: CDBNAME: R2512; COMPONENTTYPE: 4; INSTANCENAME: cmp223; VAL1: 100m(F); VAL2: 3W
R183 = R: CDBNAME: R0603_6; COMPONENTTYPE: 4; INSTANCENAME: cmp242; VAL1: 10k(J); VAL2: 100mW
R184 = R: CDBNAME: R0603_9; COMPONENTTYPE: 4; INSTANCENAME: cmp229; VAL1: 232k(B); VAL2: 63mW
R185 = R: CDBNAME: R1206; COMPONENTTYPE: 4; INSTANCENAME: cmp140; VAL1: 300m(F); VAL2: 1.5W
R191 = R: CDBNAME: R0603_2; COMPONENTTYPE: 4; INSTANCENAME: cmp212; VAL1: 2.2k(F); VAL2: 100mW
R192 = R: CDBNAME: R0603; COMPONENTTYPE: 4; INSTANCENAME: cmp244; NOTMOUNT: NOT MOUNT
SJ7 = SJ2W: CDBNAME: SJ_2; COMP: SJ_2; COMPONENTNAME: SJ; COMPONENTTYPE: 4; FUNCN: SJ; INSTANCENAME: cmp237
SJ8 = SJ2W: CDBNAME: SJ_2; COMP: SJ_2; COMPONENTNAME: SJ; COMPONENTTYPE: 4; FUNCN: SJ; INSTANCENAME: cmp143
SJ9 = SJ2W: CDBNAME: SJ_2; COMP: SJ_2; COMPONENTNAME: SJ; COMPONENTTYPE: 4; FUNCN: SJ; INSTANCENAME: cmp144
SW1 = SS_12SDP2: COMPONENTKIND: 135; COMPONENTNAME: SW; COMPONENTTYPE: 4; FUNCN: SW; INSTANCENAME: INS6128
U3 = TPD7104AF: COMPONENTNAME: IC; COMPONENTTYPE: 4; FUNCN: IC; INSTANCENAME: INS6060
U?#4 = WAKU_DEF100: COMPONENTTYPE: 2; DATE: 2021/9/30; DRAWINGNUMBER: RD209-SCHEMATIC1-01; FUNCTION: Headlight Power Supply Board 4; REVISION: 01; SHEETNUMBER: 4/4; TITLE: LED Driver Circuit for / Matrix LED Headlight; UPDATEDATE: 2021/09/30; UPDATETIME: 12:50:54
ZD44 = ZD#1: CDBNAME: ZD-16V; COMPONENTTYPE: 4; CaptureCellPackProp: ZD##1; INSTANCENAME: cmp122; NOTMOUNT: NOT MOUNT
ZD45 = ZD#1: CDBNAME: ZD-16V; COMPONENTTYPE: 4; CaptureCellPackProp: ZD##1; INSTANCENAME: cmp123; NOTMOUNT: NOT MOUNT
ZD46 = ZD#1: CDBNAME: ZD-16V; COMPONENTTYPE: 4; CaptureCellPackProp: ZD##1; INSTANCENAME: cmp119; NOTMOUNT: NOT MOUNT
ZD47 = ZD#1: CDBNAME: ZD-16V; COMPONENTTYPE: 4; CaptureCellPackProp: ZD##1; INSTANCENAME: cmp118; NOTMOUNT: NOT MOUNT
ZD61 = ZD: CDBNAME: USC; COMPONENTTYPE: 4; INSTANCENAME: cmp201; USERCOMPTEXT3: TOSHIBA; VAL1: CUZ6V8; VAL3: CUZ6V8

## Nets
+5V: C68.1 C71.1(2) CON1.1 IC4.7(VCCS) IC4.8(VCC) Q81.C R126.2 SJ8.1 SJ9.1 SW1.3
+12V: C21.1 C70.1(2) CON9.P_1(1) IC4.1(VIN) Q73.5 Q73.6 Q73.7 Q73.8 Q73.EP R185.1 U3.1(VDD)
GND: C1.1 C2.1 C3.1 C4.1 C5.1 C18.1 C19.1 C21.2 C26.1 C27.1 C28.1 C29.1 C32.1 C33.1 C34.1 C35.1 C36.1 C39.1 C40.1 C41.1 C42.1 C43.1 C46.1 C47.1 C48.1 C49.1 C50.1 C53.1 C54.1 C55.1 C56.1 C57.1 C60.1 C61.1 C62.1 C63.1 C64.1 C67.1 C69.2 C70.2(1) C71.2(1) C72.1 C73.1 C74.1 C75.1 C76.1 CON1.2 CON9.P_2(2) CON10.5 CON10.10 IC4.10(GND1) IC4.14(TP1) IC4.16(TP2) IC4.20(GND2) R2.1 R3.2 R5.2 R7.1 R8.1 R23.1 R38.1 R53.1 R68.1 R83.1 R98.1 R113.1 R125.1 R132.2 R133.2 R134.1 R136.1 R137.1 R141.2 R142.2 R143.1 R145.1 R146.1 R150.2 R151.2 R152.1 R154.1 R155.1 R159.2 R160.2 R161.1 R163.1 R164.1 R168.2 R169.2 R170.1 R172.1 R173.1 R177.2 R178.2 R179.1 R181.1 R182.1 SJ1.1 SJ2.1 SJ3.1 SJ4.1 SJ5.1 SJ6.1 SJ7.1 SJ8.3 SJ9.3 U1.2(SGND) U1.12(PGND) U1.EP U3.2(IS) U3.5(GND) U5.2(SGND) U5.12(PGND) U5.EP U6.2(SGND) U6.12(PGND) U6.EP U7.2(SGND) U7.12(PGND) U7.EP U8.2(SGND) U8.12(PGND) U8.EP U9.2(SGND) U9.12(PGND) U9.EP U10.2(SGND) U10.12(PGND) U10.EP
VCC: C1.2 C29.2 C36.2 C43.2 C50.2 C57.2 C64.2 L1.1 L2.1 L3.1 L4.1 L5.1 L6.1 L7.1 Q74.5 Q74.6 Q74.7 Q74.8 Q74.EP R1.2 R119.2 R121.2 R123.2 R135.2 R144.2 R153.2 R162.2 R171.2 R180.2 R186.2 R188.2 R190.2 R192.2 SJ1.3 SJ2.3 SJ3.3 SJ4.3 SJ5.3 SJ6.3 SJ7.3 U1.15(IN) U5.15(IN) U6.15(IN) U7.15(IN) U8.15(IN) U9.15(IN) U10.15(IN) ZD55.A ZD56.A ZD57.A ZD58.A ZD59.A ZD60.A ZD61.A
LED+1: C3.2 C18.2 CON2.2 D1.C R4.2 R118.2
LED+2: C19.2 C32.2 CON3.2 D48.C R120.2 R139.2
LED+3: C39.2 C46.2 CON4.2 D49.C R122.2 R148.2
LED+4: C53.2 C60.2 CON5.2 D50.C R124.2 R157.2
LED+5: C75.2 C76.2 CON6.2 D51.C R166.2 R187.2
LED+6: C67.2 C72.2 CON7.2 D52.C R175.2 R189.2
LED+7: C73.2 C74.2 CON8.2 D53.C R184.2 R191.2
LED-1: CON2.1 Q2.1 Q2.2 Q2.5 Q2.6
LV1: C6.1 C8.1 R9.1 R22.1 SJ1.2 U1.19(LV)
LV2: C9.1 C31.1 R37.1 R138.1 SJ2.2 U5.19(LV)
LV3: C10.1 C38.1 R52.1 R147.1 SJ3.2 U6.19(LV)
LV4: C11.1 C45.1 R67.1 R156.1 SJ4.2 U7.19(LV)
LV5: C12.1 C52.1 R82.1 R165.1 SJ5.2 U8.19(LV)
LV6: C13.1 C59.1 R97.1 R174.1 SJ6.2 U9.19(LV)
LV7: C14.1 C66.1 R112.1 R183.1 SJ7.2 U10.19(LV)
PWMDIM1: CON10.1 U1.10(PWMDIM)
PWMDIM2: CON10.6 U5.10(PWMDIM)
PWMDIM3: CON10.2 U6.10(PWMDIM)
PWMDIM4: CON10.7 U7.10(PWMDIM)
PWMDIM5: CON10.3 U8.10(PWMDIM)
PWMDIM6: CON10.8 U9.10(PWMDIM)
PWMDIM7: CON10.4 U10.10(PWMDIM)
SIG1: Q80.4 U10.13(NDRV)
SIG2: Q1.1 Q1.2 Q1.3 R8.2 U1.11(CS)
SIG212: C5.2 U1.14(VCC)
SIG213: C2.2 U1.6(SC)
SIG216: Q1.4 U1.13(NDRV)
SIG218: C7.1 R7.2
SIG223: Q2.3 R23.2 R24.1
SIG224: R133.1 U5.8(RT_SYNC)
SIG225: C28.2 U5.6(SC)
SIG229: C26.2 R131.2(1) U5.4(REF)
SIG230: C31.2 U5.17(CLV)
SIG231: C27.2 U5.14(VCC)
SIG233: R134.2 R135.1 U5.9(UVEN)
SIG235: C30.2 U5.3(COMP)
SIG236: Q75.1 Q75.2 Q75.3 R137.2 U5.11(CS)
SIG237: R138.2 R139.1 U5.1(OVP+)
SIG238: R120.1 R121.1 U5.16(HV) ZD56.K(C)
SIG243: C30.1 R136.2
SIG244: Q12.3 R38.2 R39.1
SIG245: R131.1(2) R132.1 U5.5(REFI)
SIG250: D48.A L2.2 Q75.5 Q75.6 Q75.7 Q75.8 Q75.EP
SIG251: Q75.4 U5.13(NDRV)
SIG494: R127.2 U3.6(IN)
SIG518: C69.1 IC4.15(TC)
SIG595: IC4.13(SE) SJ8.2
SIG623: ZD46.A ZD47.A
SIG625: ZD44.A ZD45.A
SIG626: Q73.1 Q73.2 Q73.3 Q74.1 Q74.2 Q74.3 R129.1 R130.2 ZD45.C ZD46.C
SIG628: Q73.4 Q74.4 R128.2 R129.2 R130.1 ZD44.C ZD47.C
SIG631: R126.1 U3.7(DIAG)
SIG632: R125.2 U3.8(REF)
SIG634: R127.1 SW1.2
SIG635: R128.1 U3.3(OUT)
SIG638: IC4.3(OUT) Q81.B
SIG639: IC4.2(VS) Q81.E R185.2
SIG642: IC4.19(WS) SJ9.2
SIG643: IC4.17(CK) P24.P_1(1)
SIG644: IC4.11(_RESET_) P23.P_1(1)
SIG662: R39.2 U5.18(DIMOUT)
SIG663: CON3.1 Q12.1 Q12.2 Q12.5 Q12.6
SIG664: C9.2 Q12.4 R37.2 U5.20(SENSE+)
SIG668: R142.1 U6.8(RT_SYNC)
SIG669: Q77.1 Q77.2 Q77.3 R155.2 U7.11(CS)
SIG670: D50.A L4.2 Q77.5 Q77.6 Q77.7 Q77.8 Q77.EP
SIG671: CON5.1 Q32.1 Q32.2 Q32.5 Q32.6
SIG673: C44.2 U7.3(COMP)
SIG674: C45.2 U7.17(CLV)
SIG675: R156.2 R157.1 U7.1(OVP+)
SIG676: R69.2 U7.18(DIMOUT)
SIG677: R147.2 R148.1 U6.1(OVP+)
SIG679: R143.2 R144.1 U6.9(UVEN)
SIG680: R151.1 U7.8(RT_SYNC)
SIG681: C42.2 U7.6(SC)
SIG682: Q32.3 R68.2 R69.1
SIG683: R54.2 U6.18(DIMOUT)
SIG686: R124.1 R186.1 U7.16(HV) ZD58.K(C)
SIG690: R149.1(2) R150.1 U7.5(REFI)
SIG691: R152.2 R153.1 U7.9(UVEN)
SIG693: C40.2 R149.2(1) U7.4(REF)
SIG694: Q77.4 U7.13(NDRV)
SIG695: C41.2 U7.14(VCC)
SIG696: C10.2 Q22.4 R52.2 U6.20(SENSE+)
SIG697: D49.A L3.2 Q76.5 Q76.6 Q76.7 Q76.8 Q76.EP
SIG698: R122.1 R123.1 U6.16(HV) ZD57.K(C)
SIG699: Q76.1 Q76.2 Q76.3 R146.2 U6.11(CS)
SIG700: C37.1 R145.2
SIG702: C44.1 R154.2
SIG704: Q22.3 R53.2 R54.1
SIG705: CON4.1 Q22.1 Q22.2 Q22.5 Q22.6
SIG707: R140.1(2) R141.1 U6.5(REFI)
SIG709: C11.2 Q32.4 R67.2 U7.20(SENSE+)
SIG710: C37.2 U6.3(COMP)
SIG711: C35.2 U6.6(SC)
SIG712: C33.2 R140.2(1) U6.4(REF)
SIG713: C38.2 U6.17(CLV)
SIG715: C34.2 U6.14(VCC)
SIG717: Q76.4 U6.13(NDRV)
SIG719: C59.2 U9.17(CLV)
SIG721: R160.1 U8.8(RT_SYNC)
SIG722: C58.2 U9.3(COMP)
SIG723: Q79.1 Q79.2 Q79.3 R173.2 U9.11(CS)
SIG724: D52.A L6.2 Q79.5 Q79.6 Q79.7 Q79.8 Q79.EP
SIG727: CON7.1 Q52.1 Q52.2 Q52.5 Q52.6
SIG729: C48.2 U8.14(VCC)
SIG730: Q78.4 U8.13(NDRV)
SIG732: R158.1(2) R159.1 U8.5(REFI)
SIG733: C49.2 U8.6(SC)
SIG735: C51.2 U8.3(COMP)
SIG736: C52.2 U8.17(CLV)
SIG737: C47.2 R158.2(1) U8.4(REF)
SIG738: C13.2 Q52.4 R97.2 U9.20(SENSE+)
SIG740: Q78.1 Q78.2 Q78.3 R164.2 U8.11(CS)
SIG741: R187.1 R188.1 U8.16(HV) ZD59.K(C)
SIG743: CON6.1 Q42.1 Q42.2 Q42.5 Q42.6
SIG744: Q42.3 R83.2 R84.1
SIG745: C51.1 R163.2
SIG746: C58.1 R172.2
SIG748: R170.2 R171.1 U9.9(UVEN)
SIG749: Q79.4 U9.13(NDRV)
SIG750: C54.2 R167.2(1) U9.4(REF)
SIG753: C55.2 U9.14(VCC)
SIG754: C12.2 Q42.4 R82.2 U8.20(SENSE+)
SIG755: D51.A L5.2 Q78.5 Q78.6 Q78.7 Q78.8 Q78.EP
SIG756: R167.1(2) R168.1 U9.5(REFI)
SIG760: R189.1 R190.1 U9.16(HV) ZD60.K(C)
SIG761: R84.2 U8.18(DIMOUT)
SIG763: R174.2 R175.1 U9.1(OVP+)
SIG764: R165.2 R166.1 U8.1(OVP+)
SIG765: C56.2 U9.6(SC)
SIG766: R99.2 U9.18(DIMOUT)
SIG767: R169.1 U9.8(RT_SYNC)
SIG768: R161.2 R162.1 U8.9(UVEN)
SIG770: Q52.3 R98.2 R99.1
SIG771: R178.1 U10.8(RT_SYNC)
SIG775: C62.2 U10.14(VCC)
SIG778: R176.1(2) R177.1 U10.5(REFI)
SIG779: C63.2 U10.6(SC)
SIG781: C65.2 U10.3(COMP)
SIG782: C66.2 U10.17(CLV)
SIG783: C61.2 R176.2(1) U10.4(REF)
SIG784: Q80.1 Q80.2 Q80.3 R182.2 U10.11(CS)
SIG785: R191.1 R192.1 U10.16(HV) ZD61.K(C)
SIG787: CON8.1 Q62.1 Q62.2 Q62.5 Q62.6
SIG788: Q62.3 R113.2 R114.1
SIG789: C65.1 R181.2
SIG791: C14.2 Q62.4 R112.2 U10.20(SENSE+)
SIG794: R114.2 U10.18(DIMOUT)
SIG795: R183.2 R184.1 U10.1(OVP+)
SIG796: R179.2 R180.1 U10.9(UVEN)
SIG800: D53.A L7.2 Q80.5 Q80.6 Q80.7 Q80.8 Q80.EP
N00268: R5.1 R6.1(2) U1.5(REFI)
N00273: R3.1 U1.8(RT_SYNC)
N00275: R1.1 R2.2 U1.9(UVEN)
N00392: D1.A L1.2 Q1.5 Q1.6 Q1.7 Q1.8 Q1.EP
N00398: C7.2 U1.3(COMP)
N00400: C6.2 U1.17(CLV)
N00402: R4.1 R9.2 U1.1(OVP+)
N00897: C8.2 Q2.4 R22.2 U1.20(SENSE+)
N00907: R24.2 U1.18(DIMOUT)
N00925: R118.1 R119.1 U1.16(HV) ZD55.K(C)
N01084: C4.2 R6.2(1) U1.4(REF)
N08892: C68.2 IC4.5(COMP)

Not connected (* = marked no-connect by the designer): CON10 9; IC4 4 6 9 12 18; SW1 1; U1 7(_FLT); U3 4(SUB); U5 7(_FLT); U6 7(_FLT); U7 7(_FLT); U8 7(_FLT); U9 7(_FLT); U10 7(_FLT)

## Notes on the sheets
sheet 1
- Boost
- Boost-Buck
- 1608
- 1608
- 3225
- 3225
- 3225
- 1608
- 1608
- 1608
- 1608
- 1608
- 2012
- 1608
- 1608
- 1608
- 6432
- 1608
- 1608
- 1608
- 6432
- 1608
- 1608
- 1608
- 1608
- 1000mA
- 3216
- 2012
- 1608
- 1608
- 1608
- 1608
- 2012
- 1608
- 1608
sheet 2
- Boost
- Boost-Buck
- 1608
- 1608
- 3225
- 3225
- 3225
- 1608
- 1608
- 1608
- 1608
- 1608
- 2012
- 1608
- 1608
- 1608
- 1608
- 1608
- 1608
- 6432
- 6432
- 1608
- 1608
- 1608
- 1608
- Boost
- Boost-Buck
- 1608
- 3225
- 1608
- 1608
- 3225
- 3225
- 1608
- 1608
- 1608
- 1608
- 1608
- 2012
- 1608
- 1608
- 1608
- 1608
- 6432
- 6432
- 1608
- 1608
- 1608
- 1608
- 1608
sheet 3
- Boost
- Boost-Buck
- 1608
- 1608
- 3225
- 3225
- 3225
- 1608
- 1608
- 1608
- 1608
- 1608
- 2012
- 1608
- 1608
- 1608
- 1608
- 1608
- 1608
- 6432
- 6432
- 1608
- 1608
- 1608
- 1608
- Boost
- Boost-Buck
- 1608
- 3225
- 1608
- 3225
- 1608
- 3225
- 1608
- 1608
- 1608
- 1608
- 1608
- 2012
- 1608
- 1608
- 1608
- 1608
- 6432
- 6432
- 1608
- 1608
- 1608
- 1608
- 1608
sheet 4
- Boost
- Boost-Buck
- 1608
- 1608
- 3225
- 3225
- 3225
- 1608
- 1608
- 1608
- 1608
- 1608
- 2012
- 1608
- 1608
- 1608
- 1608
- 1608
- 1608
- 6432
- 6432
- 1608
- 1608
- 1608
- 1608
- Boost
- Boost-Buck
- 1608
- 3225
- 1608
- 1608
- 3225
- 3225
- 1608
- 1608
- 1608
- 1608
- 1608
- 2012
- 1608
- 1608
- 1608
- 1608
- 6432
- 6432
- 1608
- 1608
- 1608
- 1608
- 1608
